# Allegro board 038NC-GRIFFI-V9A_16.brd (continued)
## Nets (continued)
DGND: BD1.1 BD2.1 BR1.2 BR3.2 BR4.2 C14.1 C84.2 C85.2 C86.2 C87.2 C88.2 C89.2 C90.2 C99.2 C100.2 C101.2 C103.2 R378.2 R382.2 SITE1.EPAD1(AVSS[01]) SITE1.F3(AVSS_F[01]) SITE1.F24(PVSS_F) SITE1.G1 SITE1.G2 SITE1.G3 SITE1.G4 SITE1.G5 SITE2.EPAD1(AVSS[01]) SITE2.F3(AVSS_F[01]) SITE2.F24(PVSS_F) SITE2.G1 SITE2.G2 SITE2.G3 SITE2.G4 SITE2.G5 SITE3.EPAD1(AVSS[01]) SITE3.F3(AVSS_F[01]) SITE3.F24(PVSS_F) SITE3.G1 SITE3.G2 SITE3.G3 SITE3.G4 SITE3.G5 SITE4.EPAD1(AVSS[01]) SITE4.F3(AVSS_F[01]) SITE4.F24(PVSS_F) SITE4.G1 SITE4.G2 SITE4.G3 SITE4.G4 SITE4.G5 SITE5.EPAD1(AVSS[01]) SITE5.F3(AVSS_F[01]) SITE5.F24(PVSS_F) SITE5.G1 SITE5.G2 SITE5.G3 SITE5.G4 SITE5.G5 SITE6.EPAD1(AVSS[01]) SITE6.F3(AVSS_F[01]) SITE6.F24(PVSS_F) SITE6.G1 SITE6.G2 SITE6.G3 SITE6.G4 SITE6.G5 SITE7.EPAD1(AVSS[01]) SITE7.F3(AVSS_F[01]) SITE7.F24(PVSS_F) SITE7.G1 SITE7.G2 SITE7.G3 SITE7.G4 SITE7.G5 SITE8.EPAD1(AVSS[01]) SITE8.F3(AVSS_F[01]) SITE8.F24(PVSS_F) SITE8.G1 SITE8.G2 SITE8.G3 SITE8.G4 SITE8.G5 SITE9.EPAD1(AVSS[01]) SITE9.F3(AVSS_F[01]) SITE9.F24(PVSS_F) SITE9.G1 SITE9.G2 SITE9.G3 SITE9.G4 SITE9.G5 SITE10.EPAD1(AVSS[01]) SITE10.F3(AVSS_F[01]) SITE10.F24(PVSS_F) SITE10.G1 SITE10.G2 SITE10.G3 SITE10.G4 SITE10.G5 SITE11.EPAD1(AVSS[01]) SITE11.F3(AVSS_F[01]) SITE11.F24(PVSS_F) SITE11.G1 SITE11.G2 SITE11.G3 SITE11.G4 SITE11.G5 SITE12.EPAD1(AVSS[01]) SITE12.F3(AVSS_F[01]) SITE12.F24(PVSS_F) SITE12.G1 SITE12.G2 SITE12.G3 SITE12.G4 SITE12.G5 SITE13.EPAD1(AVSS[01]) SITE13.F3(AVSS_F[01]) SITE13.F24(PVSS_F) SITE13.G1 SITE13.G2 SITE13.G3 SITE13.G4 SITE13.G5 SITE14.EPAD1(AVSS[01]) SITE14.F3(AVSS_F[01]) SITE14.F24(PVSS_F) SITE14.G1 SITE14.G2 SITE14.G3 SITE14.G4 SITE14.G5 SITE15.EPAD1(AVSS[01]) SITE15.F3(AVSS_F[01]) SITE15.F24(PVSS_F) SITE15.G1 SITE15.G2 SITE15.G3 SITE15.G4 SITE15.G5 SITE16.EPAD1(AVSS[01]) SITE16.F3(AVSS_F[01]) SITE16.F24(PVSS_F) SITE16.G1 SITE16.G2 SITE16.G3 SITE16.G4 SITE16.G5 SLOT0.A9 SLOT0.A10 SLOT0.A11 SLOT0.A12 SLOT0.A13 SLOT0.A14 SLOT0.A15 SLOT0.A17 SLOT0.A38 SLOT0.A42 SLOT0.A44 SLOT0.A46 SLOT0.A50 SLOT0.A52 SLOT0.A53 SLOT0.A54 SLOT0.A56 SLOT0.A57 SLOT0.A58 SLOT0.A60 SLOT0.A61 SLOT0.B9 SLOT0.B11 SLOT0.B13 SLOT0.B15 SLOT0.B17 SLOT0.B38 SLOT0.B42 SLOT0.B44 SLOT0.B46 SLOT0.B48 SLOT0.B50 SLOT0.B51 SLOT0.B52 SLOT0.B54 SLOT0.B55 SLOT0.B56 SLOT0.B58 SLOT0.B59 SLOT0.B60 SLOT0.B62 SLOT0.C9 SLOT0.C11 SLOT0.C12 SLOT0.C13 SLOT0.C15 SLOT0.C17 SLOT0.C42 SLOT0.C44 SLOT0.C46 SLOT0.C48 SLOT0.C50 SLOT0.C52 SLOT0.C53 SLOT0.C54 SLOT0.C56 SLOT0.C57 SLOT0.C58 SLOT0.C60 SLOT0.C61 SLOT0.C62 SLOT0.D9 SLOT0.D10 SLOT0.D11 SLOT0.D13 SLOT0.D14 SLOT0.D15 SLOT0.D42 SLOT0.D44 SLOT0.D46 SLOT0.D48 SLOT0.D50 SLOT0.D51 SLOT0.D52 SLOT0.D54 SLOT0.D55 SLOT0.D56 SLOT0.D58 SLOT0.D59 SLOT0.D60 SLOT0.E9 SLOT0.E11 SLOT0.E12 SLOT0.E13 SLOT0.E15 SLOT0.E42 SLOT0.E44 SLOT0.E46 SLOT0.E48 SLOT0.E50 SLOT0.E52 SLOT0.E53 SLOT0.E54 SLOT0.E56 SLOT0.E57 SLOT0.E58 SLOT0.E60 SLOT0.E61 SLOT0.E62 SLOT0.F9 SLOT0.F11 SLOT0.F13 SLOT0.F15 SLOT0.F42 SLOT0.F44 SLOT0.F46 SLOT0.F48 SLOT0.F50 SLOT0.F51 SLOT0.F52 SLOT0.F54 SLOT0.F55 SLOT0.F56 SLOT0.F58 SLOT0.F59 SLOT0.F60 SLOT0.F62 SLOT0.G10 SLOT0.G12 SLOT0.G42 SLOT0.G44 SLOT0.G46 SLOT0.G50 SLOT0.G52 SLOT0.G54 SLOT0.G56 SLOT0.G58 SLOT0.G60 SLOT3.A6 SLOT3.A8 SLOT3.A10 SLOT3.A12 SLOT3.A14 SLOT3.A16 SLOT3.A18 SLOT3.A20 SLOT3.A22 SLOT3.A24 SLOT3.A26 SLOT3.A28 SLOT3.A30 SLOT3.A32 SLOT3.A34 SLOT3.A36 SLOT3.A38 SLOT3.A40 SLOT3.A42 SLOT3.A44 SLOT3.A46 SLOT3.A48 SLOT3.A50 SLOT3.A52 SLOT3.A54 SLOT3.A56 SLOT3.A58 SLOT3.A60 SLOT3.B6 SLOT3.B8 SLOT3.B10 SLOT3.B12 SLOT3.B14 SLOT3.B16 SLOT3.B18 SLOT3.B20 SLOT3.B22 SLOT3.B24 SLOT3.B26 SLOT3.B28 SLOT3.B30 SLOT3.B32 SLOT3.B34 SLOT3.B36 SLOT3.B38 SLOT3.B40 SLOT3.B42 SLOT3.B44 SLOT3.B46 SLOT3.B48 SLOT3.B50 SLOT3.B52 SLOT3.B54 SLOT3.B56 SLOT3.B58 SLOT3.B60 SLOT3.C6 SLOT3.C8 SLOT3.C10 SLOT3.C12 SLOT3.C14 SLOT3.C16 SLOT3.C18 SLOT3.C20 SLOT3.C22 SLOT3.C24 SLOT3.C26 SLOT3.C28 SLOT3.C30 SLOT3.C32 SLOT3.C34 SLOT3.C36 SLOT3.C38 SLOT3.C40 SLOT3.C42 SLOT3.C44 SLOT3.C46 SLOT3.C48 SLOT3.C50 SLOT3.C52 SLOT3.C54 SLOT3.C56 SLOT3.C58 SLOT3.C60 SLOT3.D6 SLOT3.D8 SLOT3.D10 SLOT3.D12 SLOT3.D14 SLOT3.D16 SLOT3.D18 SLOT3.D20 SLOT3.D22 SLOT3.D24 SLOT3.D26 SLOT3.D28 SLOT3.D30 SLOT3.D32 SLOT3.D34 SLOT3.D36 SLOT3.D38 SLOT3.D40 SLOT3.D42 SLOT3.D44 SLOT3.D46 SLOT3.D48 SLOT3.D50 SLOT3.D52 SLOT3.D54 SLOT3.D56 SLOT3.D58 SLOT3.D60 SLOT3.E6 SLOT3.E8 SLOT3.E10 SLOT3.E12 SLOT3.E14 SLOT3.E16 SLOT3.E18 SLOT3.E20 SLOT3.E22 SLOT3.E24 SLOT3.E26 SLOT3.E28 SLOT3.E30 SLOT3.E32 SLOT3.E34 SLOT3.E36 SLOT3.E38 SLOT3.E40 SLOT3.E42 SLOT3.E44 SLOT3.E46 SLOT3.E48 SLOT3.E50 SLOT3.E52 SLOT3.E54 SLOT3.E56 SLOT3.E58 SLOT3.E60 SLOT3.F6 SLOT3.F8 SLOT3.F10 SLOT3.F12 SLOT3.F14 SLOT3.F16 SLOT3.F18 SLOT3.F20 SLOT3.F22 SLOT3.F24 SLOT3.F26 SLOT3.F28 SLOT3.F30 SLOT3.F32 SLOT3.F34 SLOT3.F36 SLOT3.F38 SLOT3.F40 SLOT3.F42 SLOT3.F44 SLOT3.F46 SLOT3.F48 SLOT3.F50 SLOT3.F52 SLOT3.F54 SLOT3.F56 SLOT3.F58 SLOT3.F60 SLOT4.A6 SLOT4.A8 SLOT4.A10 SLOT4.A12 SLOT4.A14 SLOT4.A16 SLOT4.A18 SLOT4.A20 SLOT4.A22 SLOT4.A24 SLOT4.A26 SLOT4.A28 SLOT4.A30 SLOT4.A32 SLOT4.A34 SLOT4.A36 SLOT4.A38 SLOT4.A40 SLOT4.A42 SLOT4.A44 SLOT4.A46 SLOT4.A48 SLOT4.A50 SLOT4.A52 SLOT4.A54 SLOT4.A56 SLOT4.A58 SLOT4.A60 SLOT4.B6 SLOT4.B8 SLOT4.B10 SLOT4.B12 SLOT4.B14 SLOT4.B16 SLOT4.B18 SLOT4.B20 SLOT4.B22 SLOT4.B24 SLOT4.B26 SLOT4.B28 SLOT4.B30 SLOT4.B32 SLOT4.B34 SLOT4.B36 SLOT4.B38 SLOT4.B40 SLOT4.B42 SLOT4.B44 SLOT4.B46 SLOT4.B48 SLOT4.B50 SLOT4.B52 SLOT4.B54 SLOT4.B56 SLOT4.B58 SLOT4.B60 SLOT4.C6 SLOT4.C8 SLOT4.C10 SLOT4.C12 SLOT4.C14 SLOT4.C16 SLOT4.C18 SLOT4.C20 SLOT4.C22 SLOT4.C24 SLOT4.C26 SLOT4.C28 SLOT4.C30 SLOT4.C32 SLOT4.C34 SLOT4.C36 SLOT4.C38 SLOT4.C40 SLOT4.C42 SLOT4.C44 SLOT4.C46 SLOT4.C48 SLOT4.C50 SLOT4.C52 SLOT4.C54 SLOT4.C56 SLOT4.C58 SLOT4.C60 SLOT4.D6 SLOT4.D8 SLOT4.D10 SLOT4.D12 SLOT4.D14 SLOT4.D16 SLOT4.D18 SLOT4.D20 SLOT4.D22 SLOT4.D24 SLOT4.D26 SLOT4.D28 SLOT4.D30 SLOT4.D32 SLOT4.D34 SLOT4.D36 SLOT4.D38 SLOT4.D40 SLOT4.D42 SLOT4.D44 SLOT4.D46 SLOT4.D48 SLOT4.D50 SLOT4.D52 SLOT4.D54 SLOT4.D56 SLOT4.D58 SLOT4.D60 SLOT4.E6 SLOT4.E8 SLOT4.E10 SLOT4.E12 SLOT4.E14 SLOT4.E16 SLOT4.E18 SLOT4.E20 SLOT4.E22 SLOT4.E24 SLOT4.E26 SLOT4.E28 SLOT4.E30 SLOT4.E32 SLOT4.E34 SLOT4.E36 SLOT4.E38 SLOT4.E40 SLOT4.E42 SLOT4.E44 SLOT4.E46 SLOT4.E48 SLOT4.E50 SLOT4.E52 SLOT4.E54 SLOT4.E56 SLOT4.E58 SLOT4.E60 SLOT4.F6 SLOT4.F8 SLOT4.F10 SLOT4.F12 SLOT4.F14 SLOT4.F16 SLOT4.F18 SLOT4.F20 SLOT4.F22 SLOT4.F24 SLOT4.F26 SLOT4.F28 SLOT4.F30 SLOT4.F32 SLOT4.F34 SLOT4.F36 SLOT4.F38 SLOT4.F40 SLOT4.F42 SLOT4.F44 SLOT4.F46 SLOT4.F48 SLOT4.F50 SLOT4.F52 SLOT4.F54 SLOT4.F56 SLOT4.F58 SLOT4.F60 SLOT6.A2 SLOT6.A6 SLOT6.A10 SLOT6.A14 SLOT6.A18 SLOT6.A22 SLOT6.A26 SLOT6.A30 SLOT6.A34 SLOT6.A38 SLOT6.A42 SLOT6.A46 SLOT6.A50 SLOT6.A54 SLOT6.A58 SLOT6.B4 SLOT6.B8 SLOT6.B12 SLOT6.B16 SLOT6.B20 SLOT6.B24 SLOT6.B28 SLOT6.B32 SLOT6.B36 SLOT6.B40 SLOT6.B44 SLOT6.B48 SLOT6.B52 SLOT6.B56 SLOT6.B60 SLOT6.C2 SLOT6.C6 SLOT6.C10 SLOT6.C14 SLOT6.C18 SLOT6.C22 SLOT6.C26 SLOT6.C30 SLOT6.C34 SLOT6.C38 SLOT6.C42 SLOT6.C46 SLOT6.C50 SLOT6.C54 SLOT6.C58 SLOT6.D4 SLOT6.D8 SLOT6.D12 SLOT6.D16 SLOT6.D20 SLOT6.D24 SLOT6.D28 SLOT6.D32 SLOT6.D36 SLOT6.D40 SLOT6.D44 SLOT6.D48 SLOT6.D52 SLOT6.D56 SLOT6.D60 SLOT6.E2 SLOT6.E6 SLOT6.E10 SLOT6.E14 SLOT6.E18 SLOT6.E22 SLOT6.E26 SLOT6.E30 SLOT6.E34 SLOT6.E38 SLOT6.E42 SLOT6.E46 SLOT6.E50 SLOT6.E54 SLOT6.E58 SLOT6.F4 SLOT6.F8 SLOT6.F12 SLOT6.F16 SLOT6.F20 SLOT6.F24 SLOT6.F28 SLOT6.F32 SLOT6.F36 SLOT6.F40 SLOT6.F44 SLOT6.F48 SLOT6.F52 SLOT6.F56 SLOT6.F60 SLOT6.G2 SLOT6.G6 SLOT6.G10 SLOT6.G14 SLOT6.G18 SLOT6.G22 SLOT6.G26 SLOT6.G30 SLOT6.G34 SLOT6.G38 SLOT6.G42 SLOT6.G46 SLOT6.G50 SLOT6.G54 SLOT6.G58 SLOT7.A2 SLOT7.A6 SLOT7.A10 SLOT7.A14 SLOT7.A18 SLOT7.A22 SLOT7.A26 SLOT7.A30 SLOT7.A34 SLOT7.A38 SLOT7.A42 SLOT7.A46 SLOT7.A50 SLOT7.A54 SLOT7.A58 SLOT7.B4 SLOT7.B8 SLOT7.B12 SLOT7.B16 SLOT7.B20 SLOT7.B24 SLOT7.B28 SLOT7.B32 SLOT7.B36 SLOT7.B40 SLOT7.B44 SLOT7.B48 SLOT7.B52 SLOT7.B56 SLOT7.B60 SLOT7.C2 SLOT7.C6 SLOT7.C10 SLOT7.C14 SLOT7.C18 SLOT7.C22 SLOT7.C26 SLOT7.C30 SLOT7.C34 SLOT7.C38 SLOT7.C42 SLOT7.C46 SLOT7.C50 SLOT7.C54 SLOT7.C58 SLOT7.D4 SLOT7.D8 SLOT7.D12 SLOT7.D16 SLOT7.D20 SLOT7.D24 SLOT7.D28 SLOT7.D32 SLOT7.D36 SLOT7.D40 SLOT7.D44 SLOT7.D48 SLOT7.D52 SLOT7.D56 SLOT7.D60 SLOT7.E2 SLOT7.E6 SLOT7.E10 SLOT7.E14 SLOT7.E18 SLOT7.E22 SLOT7.E26 SLOT7.E30 SLOT7.E34 SLOT7.E38 SLOT7.E42 SLOT7.E46 SLOT7.E50 SLOT7.E54 SLOT7.E58 SLOT7.F4 SLOT7.F8 SLOT7.F12 SLOT7.F16 SLOT7.F20 SLOT7.F24 SLOT7.F28 SLOT7.F32 SLOT7.F36 SLOT7.F40 SLOT7.F44 SLOT7.F48 SLOT7.F52 SLOT7.F56 SLOT7.F60 SLOT7.G2 SLOT7.G6 SLOT7.G10 SLOT7.G14 SLOT7.G18 SLOT7.G22 SLOT7.G26 SLOT7.G30 SLOT7.G34 SLOT7.G38 SLOT7.G42 SLOT7.G46 SLOT7.G50 SLOT7.G54 SLOT7.G58 SLOT8.A2 SLOT8.A6 SLOT8.A10 SLOT8.A14 SLOT8.A18 SLOT8.A22 SLOT8.A26 SLOT8.A30 SLOT8.A34 SLOT8.A38 SLOT8.A42 SLOT8.A46 SLOT8.A50 SLOT8.A54 SLOT8.A58 SLOT8.B4 SLOT8.B8 SLOT8.B12 SLOT8.B16 SLOT8.B20 SLOT8.B24 SLOT8.B28 SLOT8.B32 SLOT8.B36 SLOT8.B40 SLOT8.B44 SLOT8.B48 SLOT8.B52 SLOT8.B56 SLOT8.B60 SLOT8.C2 SLOT8.C6 SLOT8.C10 SLOT8.C14 SLOT8.C18 SLOT8.C22 SLOT8.C26 SLOT8.C30 SLOT8.C34 SLOT8.C38 SLOT8.C42 SLOT8.C46 SLOT8.C50 SLOT8.C54 SLOT8.C58 SLOT8.D4 SLOT8.D8 SLOT8.D12 SLOT8.D16 SLOT8.D20 SLOT8.D24 SLOT8.D28 SLOT8.D32 SLOT8.D36 SLOT8.D40 SLOT8.D44 SLOT8.D48 SLOT8.D52 SLOT8.D56 SLOT8.D60 SLOT8.E2 SLOT8.E6 SLOT8.E10 SLOT8.E14 SLOT8.E18 SLOT8.E22 SLOT8.E26 SLOT8.E30 SLOT8.E34 SLOT8.E38 SLOT8.E42 SLOT8.E46 SLOT8.E50 SLOT8.E54 SLOT8.E58 SLOT8.F4 SLOT8.F8 SLOT8.F12 SLOT8.F16 SLOT8.F20 SLOT8.F24 SLOT8.F28 SLOT8.F32 SLOT8.F36 SLOT8.F40 SLOT8.F44 SLOT8.F48 SLOT8.F52 SLOT8.F56 SLOT8.F60 SLOT8.G2 SLOT8.G6 SLOT8.G10 SLOT8.G14 SLOT8.G18 SLOT8.G22 SLOT8.G26 SLOT8.G30 SLOT8.G34 SLOT8.G38 SLOT8.G42 SLOT8.G46 SLOT8.G50 SLOT8.G54 SLOT8.G58 SLOT9.A2 SLOT9.A6 SLOT9.A10 SLOT9.A14 SLOT9.A18 SLOT9.A22 SLOT9.A26 SLOT9.A30 SLOT9.A34 SLOT9.A38 SLOT9.A42 SLOT9.A46 SLOT9.A50 SLOT9.A54 SLOT9.A58 SLOT9.B4 SLOT9.B8 SLOT9.B12 SLOT9.B16 SLOT9.B20 SLOT9.B24 SLOT9.B28 SLOT9.B32 SLOT9.B36 SLOT9.B40 SLOT9.B44 SLOT9.B48 SLOT9.B52 SLOT9.B56 SLOT9.B60 SLOT9.C2 SLOT9.C6 SLOT9.C10 SLOT9.C14 SLOT9.C18 SLOT9.C22 SLOT9.C26 SLOT9.C30 SLOT9.C34 SLOT9.C38 SLOT9.C42 SLOT9.C46 SLOT9.C50 SLOT9.C54 SLOT9.C58 SLOT9.D4 SLOT9.D8 SLOT9.D12 SLOT9.D16 SLOT9.D20 SLOT9.D24 SLOT9.D28 SLOT9.D32 SLOT9.D36 SLOT9.D40 SLOT9.D44 SLOT9.D48 SLOT9.D52 SLOT9.D56 SLOT9.D60 SLOT9.E2 SLOT9.E6 SLOT9.E10 SLOT9.E14 SLOT9.E18 SLOT9.E22 SLOT9.E26 SLOT9.E30 SLOT9.E34 SLOT9.E38 SLOT9.E42 SLOT9.E46 SLOT9.E50 SLOT9.E54 SLOT9.E58 SLOT9.F4 SLOT9.F8 SLOT9.F12 SLOT9.F16 SLOT9.F20 SLOT9.F24 SLOT9.F28 SLOT9.F32 SLOT9.F36 SLOT9.F40 SLOT9.F44 SLOT9.F48 SLOT9.F52 SLOT9.F56 SLOT9.F60 SLOT9.G2 SLOT9.G6 SLOT9.G10 SLOT9.G14 SLOT9.G18 SLOT9.G22 SLOT9.G26 SLOT9.G30 SLOT9.G34 SLOT9.G38 SLOT9.G42 SLOT9.G46 SLOT9.G50 SLOT9.G54 SLOT9.G58 SLOT10.A2 SLOT10.A6 SLOT10.A10 SLOT10.A14 SLOT10.A18 SLOT10.A22 SLOT10.A26 SLOT10.A30 SLOT10.A34 SLOT10.A38 SLOT10.A42 SLOT10.A46 SLOT10.A50 SLOT10.A54 SLOT10.A58 SLOT10.B4 SLOT10.B8 SLOT10.B12 SLOT10.B16 SLOT10.B20 SLOT10.B24 SLOT10.B28 SLOT10.B32 SLOT10.B36 SLOT10.B40 SLOT10.B44 SLOT10.B48 SLOT10.B52 SLOT10.B56 SLOT10.B60 SLOT10.C2 SLOT10.C6 SLOT10.C10 SLOT10.C14 SLOT10.C18 SLOT10.C22 SLOT10.C26 SLOT10.C30 SLOT10.C34 SLOT10.C38 SLOT10.C42 SLOT10.C46 SLOT10.C50 SLOT10.C54 SLOT10.C58 SLOT10.D4 SLOT10.D8 SLOT10.D12 SLOT10.D16 SLOT10.D20 SLOT10.D24 SLOT10.D28 SLOT10.D32 SLOT10.D36 SLOT10.D40 SLOT10.D44 SLOT10.D48 SLOT10.D52 SLOT10.D56 SLOT10.D60 SLOT10.E2 SLOT10.E6 SLOT10.E10 SLOT10.E14 SLOT10.E18 SLOT10.E22 SLOT10.E26 SLOT10.E30 SLOT10.E34 SLOT10.E38 SLOT10.E42 SLOT10.E46 SLOT10.E50 SLOT10.E54 SLOT10.E58 SLOT10.F4 SLOT10.F8 SLOT10.F12 SLOT10.F16 SLOT10.F20 SLOT10.F24 SLOT10.F28 SLOT10.F32 SLOT10.F36 SLOT10.F40 SLOT10.F44 SLOT10.F48 SLOT10.F52 SLOT10.F56 SLOT10.F60 SLOT10.G2 SLOT10.G6 SLOT10.G10 SLOT10.G14 SLOT10.G18 SLOT10.G22 SLOT10.G26 SLOT10.G30 SLOT10.G34 SLOT10.G38 SLOT10.G42 SLOT10.G46 SLOT10.G50 SLOT10.G54 SLOT10.G58 SLOT13.A2 SLOT13.A6 SLOT13.A10 SLOT13.A14 SLOT13.A18 SLOT13.A22 SLOT13.A26 SLOT13.A30 SLOT13.A34 SLOT13.A38 SLOT13.A42 SLOT13.A46 SLOT13.A50 SLOT13.A54 SLOT13.A58 SLOT13.B4 SLOT13.B8 SLOT13.B12 SLOT13.B16 SLOT13.B20 SLOT13.B24 SLOT13.B28 SLOT13.B32 SLOT13.B36 SLOT13.B40 SLOT13.B44 SLOT13.B48 SLOT13.B52 SLOT13.B56 SLOT13.B60 SLOT13.C2 SLOT13.C6 SLOT13.C10 SLOT13.C14 SLOT13.C18 SLOT13.C22 SLOT13.C26 SLOT13.C30 SLOT13.C34 SLOT13.C38 SLOT13.C42 SLOT13.C46 SLOT13.C50 SLOT13.C54 SLOT13.C58 SLOT13.D4 SLOT13.D8 SLOT13.D12 SLOT13.D16 SLOT13.D20 SLOT13.D24 SLOT13.D28 SLOT13.D32 SLOT13.D36 SLOT13.D40 SLOT13.D44 SLOT13.D48 SLOT13.D52 SLOT13.D56 SLOT13.D60 SLOT13.E2 SLOT13.E6 SLOT13.E10 SLOT13.E14 SLOT13.E18 SLOT13.E22 SLOT13.E26 SLOT13.E30 SLOT13.E34 SLOT13.E38 SLOT13.E42 SLOT13.E46 SLOT13.E50 SLOT13.E54 SLOT13.E58 SLOT13.F4 SLOT13.F8 SLOT13.F12 SLOT13.F16 SLOT13.F20 SLOT13.F24 SLOT13.F28 SLOT13.F32 SLOT13.F36 SLOT13.F40 SLOT13.F44 SLOT13.F48 SLOT13.F52 SLOT13.F56 SLOT13.F60 SLOT13.G2 SLOT13.G6 SLOT13.G10 SLOT13.G14 SLOT13.G18 SLOT13.G22 SLOT13.G26 SLOT13.G30 SLOT13.G34 SLOT13.G38 SLOT13.G42 SLOT13.G46 SLOT13.G50 SLOT13.G54 SLOT13.G58 SLOT17.A6 SLOT17.A8 SLOT17.A10 SLOT17.A12 SLOT17.A14 SLOT17.A16 SLOT17.A18 SLOT17.A20 SLOT17.A22 SLOT17.A24 SLOT17.A26 SLOT17.A28 SLOT17.A30 SLOT17.A32 SLOT17.A34 SLOT17.A36 SLOT17.A38 SLOT17.A40 SLOT17.A42 SLOT17.A44 SLOT17.A46 SLOT17.A48 SLOT17.A50 SLOT17.A52 SLOT17.A54 SLOT17.A56 SLOT17.A58 SLOT17.A60 SLOT17.B6 SLOT17.B8 SLOT17.B10 SLOT17.B12 SLOT17.B14 SLOT17.B16 SLOT17.B18 SLOT17.B20 SLOT17.B22 SLOT17.B24 SLOT17.B26 SLOT17.B28 SLOT17.B30 SLOT17.B32 SLOT17.B34 SLOT17.B36 SLOT17.B38 SLOT17.B40 SLOT17.B42 SLOT17.B44 SLOT17.B46 SLOT17.B48 SLOT17.B50 SLOT17.B52 SLOT17.B54 SLOT17.B56 SLOT17.B58 SLOT17.B60 SLOT17.C6 SLOT17.C8 SLOT17.C10 SLOT17.C12 SLOT17.C14 SLOT17.C16 SLOT17.C18 SLOT17.C20 SLOT17.C22 SLOT17.C24 SLOT17.C26 SLOT17.C28 SLOT17.C30 SLOT17.C32 SLOT17.C34 SLOT17.C36 SLOT17.C38 SLOT17.C40 SLOT17.C42 SLOT17.C44 SLOT17.C46 SLOT17.C48 SLOT17.C50 SLOT17.C52 SLOT17.C54 SLOT17.C56 SLOT17.C58 SLOT17.C60 SLOT17.D6 SLOT17.D8 SLOT17.D10 SLOT17.D12 SLOT17.D14 SLOT17.D16 SLOT17.D18 SLOT17.D20 SLOT17.D22 SLOT17.D24 SLOT17.D26 SLOT17.D28 SLOT17.D30 SLOT17.D32 SLOT17.D34 SLOT17.D36 SLOT17.D38 SLOT17.D40 SLOT17.D42 SLOT17.D44 SLOT17.D46 SLOT17.D48 SLOT17.D50 SLOT17.D52 SLOT17.D54 SLOT17.D56 SLOT17.D58 SLOT17.D60 SLOT17.E6 SLOT17.E8 SLOT17.E10 SLOT17.E12 SLOT17.E14 SLOT17.E16 SLOT17.E18 SLOT17.E20 SLOT17.E22 SLOT17.E24 SLOT17.E26 SLOT17.E28 SLOT17.E30 SLOT17.E32 SLOT17.E34 SLOT17.E36 SLOT17.E38 SLOT17.E40 SLOT17.E42 SLOT17.E44 SLOT17.E46 SLOT17.E48 SLOT17.E50 SLOT17.E52 SLOT17.E54 SLOT17.E56 SLOT17.E58 SLOT17.E60 SLOT17.F6 SLOT17.F8 SLOT17.F10 SLOT17.F12 SLOT17.F14 SLOT17.F16 SLOT17.F18 SLOT17.F20 SLOT17.F22 SLOT17.F24 SLOT17.F26 SLOT17.F28 SLOT17.F30 SLOT17.F32 SLOT17.F34 SLOT17.F36 SLOT17.F38 SLOT17.F40 SLOT17.F42 SLOT17.F44 SLOT17.F46 SLOT17.F48 SLOT17.F50 SLOT17.F52 SLOT17.F54 SLOT17.F56 SLOT17.F58 SLOT17.F60 SLOT19.A6 SLOT19.A8 SLOT19.A10 SLOT19.A12 SLOT19.A14 SLOT19.A16 SLOT19.A18 SLOT19.A20 SLOT19.A22 SLOT19.A24 SLOT19.A26 SLOT19.A28 SLOT19.A30 SLOT19.A32 SLOT19.A34 SLOT19.A36 SLOT19.A38 SLOT19.A40 SLOT19.A42 SLOT19.A44 SLOT19.A46 SLOT19.A48 SLOT19.A50 SLOT19.A52 SLOT19.A54 SLOT19.A56 SLOT19.A58 SLOT19.A60 SLOT19.B6 SLOT19.B8 SLOT19.B10 SLOT19.B12 SLOT19.B14 SLOT19.B16 SLOT19.B18 SLOT19.B20 SLOT19.B22 SLOT19.B24 SLOT19.B26 SLOT19.B28 SLOT19.B30 SLOT19.B32 SLOT19.B34 SLOT19.B36 SLOT19.B38 SLOT19.B40 SLOT19.B42 SLOT19.B44 SLOT19.B46 SLOT19.B48 SLOT19.B50 SLOT19.B52 SLOT19.B54 SLOT19.B56 SLOT19.B58 SLOT19.B60 SLOT19.C6 SLOT19.C8 SLOT19.C10 SLOT19.C12 SLOT19.C14 SLOT19.C16 SLOT19.C18 SLOT19.C20 SLOT19.C22 SLOT19.C24 SLOT19.C26 SLOT19.C28 SLOT19.C30 SLOT19.C32 SLOT19.C34 SLOT19.C36 SLOT19.C38 SLOT19.C40 SLOT19.C42 SLOT19.C44 SLOT19.C46 SLOT19.C48 SLOT19.C50 SLOT19.C52 SLOT19.C54 SLOT19.C56 SLOT19.C58 SLOT19.C60 SLOT19.D6 SLOT19.D8 SLOT19.D10 SLOT19.D12 SLOT19.D14 SLOT19.D16 SLOT19.D18 SLOT19.D20 SLOT19.D22 SLOT19.D24 SLOT19.D26 SLOT19.D28 SLOT19.D30 SLOT19.D32 SLOT19.D34 SLOT19.D36 SLOT19.D38 SLOT19.D40 SLOT19.D42 SLOT19.D44 SLOT19.D46 SLOT19.D48 SLOT19.D50 SLOT19.D52 SLOT19.D54 SLOT19.D56 SLOT19.D58 SLOT19.D60 SLOT19.E6 SLOT19.E8 SLOT19.E10 SLOT19.E12 SLOT19.E14 SLOT19.E16 SLOT19.E18 SLOT19.E20 SLOT19.E22 SLOT19.E24 SLOT19.E26 SLOT19.E28 SLOT19.E30 SLOT19.E32 SLOT19.E34 SLOT19.E36 SLOT19.E38 SLOT19.E40 SLOT19.E42 SLOT19.E44 SLOT19.E46 SLOT19.E48 SLOT19.E50 SLOT19.E52 SLOT19.E54 SLOT19.E56 SLOT19.E58 SLOT19.E60 SLOT19.F6 SLOT19.F8 SLOT19.F10 SLOT19.F12 SLOT19.F14 SLOT19.F16 SLOT19.F18 SLOT19.F20 SLOT19.F22 SLOT19.F24 SLOT19.F26 SLOT19.F28 SLOT19.F30 SLOT19.F32 SLOT19.F34 SLOT19.F36 SLOT19.F38 SLOT19.F40 SLOT19.F42 SLOT19.F44 SLOT19.F46 SLOT19.F48 SLOT19.F50 SLOT19.F52 SLOT19.F54 SLOT19.F56 SLOT19.F58 SLOT19.F60 TP_EEP_GND.1(TP) TP_EPP_SCLK_DGND1.1(TP) TP_EPP_SDA_DGND1.1(TP) TP_EPP_VCC_DGND1.1(TP) TP_REG1_P3V3.1(TP) TP_REG1_P_5V_DGND.1(TP) TP_REG1_P_10V_DGND.1(TP) TP_SDUP5V1.1(TP) TP_SDUP15V1.1(TP) TP_USER_GND1.1(TP) TP_USER_SCLK1_DGND1.1(TP) TP_USER_SDA1_DGND1.1(TP) U4.3(A0) U4.4(A1) U4.11(GND) U4.17(EP) U6.1(A0) U6.2(A1) U6.3(A2) U6.4(GND) U6.7(WP) U44.2(GND) UNK0BS1.2 UNK0BS2.2 UNK1C1.2 UNK1C2.1 UNK1C3.2 UNK1C4.1 UNK1C5.2 UNK1C6.2 UNK1C7.2 UNK1C8.2 UNK1C9.2 UNK1C12.2 UNK1CS1.2 UNK1CS4.1 UNK1CS5.1 UNK1CS19.2 UNK1CS20.2 UNK1CS21.2 UNK1CS22.2 UNK1CS23.2 UNK1CS25.2 UNK1CS26.1 UNK1CS27.1 UNK1CS28.2 UNK1R1.1 UNK1R2.2 UNK1R3.2 UNK1R42.2 UNK1RS3.1 UNK1RS4.1 UNK1U1.4 UNK2C1.2 UNK2C2.1 UNK2C3.2 UNK2C4.1 UNK2C5.2 UNK2C6.2 UNK2C7.2 UNK2C8.2 UNK2C9.2 UNK2C12.2 UNK2CS1.2 UNK2CS4.1 UNK2CS5.1 UNK2CS19.2 UNK2CS20.2 UNK2CS21.2 UNK2CS22.2 UNK2CS23.2 UNK2CS25.2 UNK2CS26.1 UNK2CS27.1 UNK2CS28.2 UNK2R1.1 UNK2R2.2 UNK2R3.2 UNK2R42.2 UNK2RS3.1 UNK2RS4.1 UNK2U1.4 UNK3C1.2 UNK3C2.1 UNK3C3.2 UNK3C4.1 UNK3C5.2 UNK3C6.2 UNK3C7.2 UNK3C8.2 UNK3C9.2 UNK3C12.2 UNK3CS1.2 UNK3CS4.1 UNK3CS5.1 UNK3CS19.2 UNK3CS20.2 UNK3CS21.2 UNK3CS22.2 UNK3CS23.2 UNK3CS25.2 UNK3CS26.1 UNK3CS27.1 UNK3CS28.2 UNK3R1.1 UNK3R2.2 UNK3R3.2 UNK3R42.2 UNK3RS3.1 UNK3RS4.1 UNK3U1.4 UNK4C1.2 UNK4C2.1 UNK4C3.2 UNK4C4.1 UNK4C5.2 UNK4C6.2 UNK4C7.2 UNK4C8.2 UNK4C9.2 UNK4C12.2 UNK4CS1.2 UNK4CS4.1 UNK4CS5.1 UNK4CS19.2 UNK4CS20.2 UNK4CS21.2 UNK4CS22.2 UNK4CS23.2 UNK4CS25.2 UNK4CS26.1 UNK4CS27.1 UNK4CS28.2 UNK4R1.1 UNK4R2.2 UNK4R3.2 UNK4R42.2 UNK4RS3.1 UNK4RS4.1 UNK4U1.4 UNK5C1.2 UNK5C2.1 UNK5C3.2 UNK5C4.1 UNK5C5.2 UNK5C6.2 UNK5C7.2 UNK5C8.2 UNK5C9.2 UNK5C12.2 UNK5CS1.2 UNK5CS4.1 UNK5CS5.1 UNK5CS19.2 UNK5CS20.2 UNK5CS21.2 UNK5CS22.2 UNK5CS23.2 UNK5CS25.2 UNK5CS26.1 UNK5CS27.1 UNK5CS28.2 UNK5R1.1 UNK5R2.2 UNK5R3.2 UNK5R42.2 UNK5RS3.1 UNK5RS4.1 UNK5U1.4 UNK6C1.2 UNK6C2.1 UNK6C3.2 UNK6C4.1 UNK6C5.2 UNK6C6.2 UNK6C7.2 UNK6C8.2 UNK6C9.2 UNK6C12.2 UNK6CS1.2 UNK6CS4.1 UNK6CS5.1 UNK6CS19.2 UNK6CS20.2 UNK6CS21.2 UNK6CS22.2 UNK6CS23.2 UNK6CS25.2 UNK6CS26.1 UNK6CS27.1 UNK6CS28.2 UNK6R1.1 UNK6R2.2 UNK6R3.2 UNK6R42.2 UNK6RS3.1 UNK6RS4.1 UNK6U1.4 UNK7C1.2 UNK7C2.1 UNK7C3.2 UNK7C4.1 UNK7C5.2 UNK7C6.2 UNK7C7.2 UNK7C8.2 UNK7C9.2 UNK7C12.2 UNK7CS1.2 UNK7CS4.1 UNK7CS5.1 UNK7CS19.2 UNK7CS20.2 UNK7CS21.2 UNK7CS22.2 UNK7CS23.2 UNK7CS25.2 UNK7CS26.1 UNK7CS27.1 UNK7CS28.2 UNK7R1.1 UNK7R2.2 UNK7R3.2 UNK7R42.2 UNK7RS3.1 UNK7RS4.1 UNK7U1.4 UNK8C1.2 UNK8C2.1 UNK8C3.2 UNK8C4.1 UNK8C5.2 UNK8C6.2 UNK8C7.2 UNK8C8.2 UNK8C9.2 UNK8C12.2 UNK8CS1.2 UNK8CS4.1 UNK8CS5.1 UNK8CS19.2 UNK8CS20.2 UNK8CS21.2 UNK8CS22.2 UNK8CS23.2 UNK8CS25.2 UNK8CS26.1 UNK8CS27.1 UNK8CS28.2 UNK8R1.1 UNK8R2.2 UNK8R3.2 UNK8R42.2 UNK8RS3.1 UNK8RS4.1 UNK8U1.4 UNK9C1.2 UNK9C2.1 UNK9C3.2 UNK9C4.1 UNK9C5.2 UNK9C6.2 UNK9C7.2 UNK9C8.2 UNK9C9.2 UNK9C12.2 UNK9CS1.2 UNK9CS4.1 UNK9CS5.1 UNK9CS19.2 UNK9CS20.2 UNK9CS21.2 UNK9CS22.2 UNK9CS23.2 UNK9CS25.2 UNK9CS26.1 UNK9CS27.1 UNK9CS28.2 UNK9R1.1 UNK9R2.2 UNK9R3.2 UNK9R42.2 UNK9RS3.1 UNK9RS4.1 UNK9U1.4 UNK10C1.2 UNK10C2.1 UNK10C3.2 UNK10C4.1 UNK10C5.2 UNK10C6.2 UNK10C7.2 UNK10C8.2 UNK10C9.2 UNK10C12.2 UNK10CS1.2 UNK10CS4.1 UNK10CS5.1 UNK10CS19.2 UNK10CS20.2 UNK10CS21.2 UNK10CS22.2 UNK10CS23.2 UNK10CS25.2 UNK10CS26.1 UNK10CS27.1 UNK10CS28.2 UNK10R1.1 UNK10R2.2 UNK10R3.2 UNK10R42.2 UNK10RS3.1 UNK10RS4.1 UNK10U1.4 UNK11C1.2 UNK11C2.1 UNK11C3.2 UNK11C4.1 UNK11C5.2 UNK11C6.2 UNK11C7.2 UNK11C8.2 UNK11C9.2 UNK11C12.2 UNK11CS1.2 UNK11CS4.1 UNK11CS5.1 UNK11CS19.2 UNK11CS20.2 UNK11CS21.2 UNK11CS22.2 UNK11CS23.2 UNK11CS25.2 UNK11CS26.1 UNK11CS27.1 UNK11CS28.2 UNK11R1.1 UNK11R2.2 UNK11R3.2 UNK11R42.2 UNK11RS3.1 UNK11RS4.1 UNK11U1.4 UNK12C1.2 UNK12C2.1 UNK12C3.2 UNK12C4.1 UNK12C5.2 UNK12C6.2 UNK12C7.2 UNK12C8.2 UNK12C9.2 UNK12C12.2 UNK12CS1.2 UNK12CS4.1 UNK12CS5.1 UNK12CS19.2 UNK12CS20.2 UNK12CS21.2 UNK12CS22.2 UNK12CS23.2 UNK12CS25.2 UNK12CS26.1 UNK12CS27.1 UNK12CS28.2 UNK12R1.1 UNK12R2.2 UNK12R3.2 UNK12R42.2 UNK12RS3.1 UNK12RS4.1 UNK12U1.4 UNK13C1.2 UNK13C2.1 UNK13C3.2 UNK13C4.1 UNK13C5.2 UNK13C6.2 UNK13C7.2 UNK13C8.2 UNK13C9.2 UNK13C12.2 UNK13CS1.2 UNK13CS4.1 UNK13CS5.1 UNK13CS19.2 UNK13CS20.2 UNK13CS21.2 UNK13CS22.2 UNK13CS23.2 UNK13CS25.2 UNK13CS26.1 UNK13CS27.1 UNK13CS28.2 UNK13R1.1 UNK13R2.2 UNK13R3.2 UNK13R42.2 UNK13RS3.1 UNK13RS4.1 UNK13U1.4 UNK14C1.2 UNK14C2.1 UNK14C3.2 UNK14C4.1 UNK14C5.2 UNK14C6.2 UNK14C7.2 UNK14C8.2 UNK14C9.2 UNK14C12.2 UNK14CS1.2 UNK14CS4.1 UNK14CS5.1 UNK14CS19.2 UNK14CS20.2 UNK14CS21.2 UNK14CS22.2 UNK14CS23.2 UNK14CS25.2 UNK14CS26.1 UNK14CS27.1 UNK14CS28.2 UNK14R1.1 UNK14R2.2 UNK14R3.2 UNK14R42.2 UNK14RS3.1 UNK14RS4.1 UNK14U1.4 UNK15C1.2 UNK15C2.1 UNK15C3.2 UNK15C4.1 UNK15C5.2 UNK15C6.2 UNK15C7.2 UNK15C8.2 UNK15C9.2 UNK15C12.2 UNK15CS1.2 UNK15CS4.1 UNK15CS5.1 UNK15CS19.2 UNK15CS20.2 UNK15CS21.2 UNK15CS22.2 UNK15CS23.2 UNK15CS25.2 UNK15CS26.1 UNK15CS27.1 UNK15CS28.2 UNK15R1.1 UNK15R2.2 UNK15R3.2 UNK15R42.2 UNK15RS3.1 UNK15RS4.1 UNK15U1.4 UNK16C1.2 UNK16C2.1 UNK16C3.2 UNK16C4.1 UNK16C5.2 UNK16C6.2 UNK16C7.2 UNK16C8.2 UNK16C9.2 UNK16C12.2 UNK16CS1.2 UNK16CS4.1 UNK16CS5.1 UNK16CS19.2 UNK16CS20.2 UNK16CS21.2 UNK16CS22.2 UNK16CS23.2 UNK16CS25.2 UNK16CS26.1 UNK16CS27.1 UNK16CS28.2 UNK16R1.1 UNK16R2.2 UNK16R3.2 UNK16R42.2 UNK16RS3.1 UNK16RS4.1 UNK16U1.4 USER_-5V1.1(A)
P5V1: C102.1 FUSE2.2 SDUP5V1.1(TP) U44.1(VIN) U44.3(EN)
P15V1: C99.1 FUSE1.2 SDUP15V1.1(TP) U46.3(IN)
AWGNH1: SLOT0.B53
AWGNH1_MARKER: SLOT0.A45
AWGNH2: SLOT0.C51
AWGNH2_MARKER: SLOT0.B45
AWGNH3: SLOT0.D53
AWGNH3_MARKER: SLOT0.F45
AWGNH4: SLOT0.E51
AWGNH4_MARKER: SLOT0.E45
AWGNH_1_2_TRIG: SLOT0.C47
AWGNH_3_4_TRIG: SLOT0.D47
CLK100_N: SLOT0.E10
CLK100_P: SLOT0.F10
CLKREF50_N: SLOT0.B10
CLKREF50_P: SLOT0.C10
DIGNH1: SLOT0.B61
DIGNH1_DC_OFFSET: SLOT0.C45
DIGNH1_TRIG: SLOT0.B49
DIGNH2: SLOT0.C59
DIGNH2_DC_OFFSET: SLOT0.A43
DIGNH2_TRIG: SLOT0.C49
DIGNH3: SLOT0.B57
DIGNH3_DC_OFFSET: SLOT0.B43
DIGNH3_TRIG: SLOT0.A47
DIGNH4: SLOT0.C55
DIGNH4_DC_OFFSET: SLOT0.C43
DIGNH4_TRIG: SLOT0.B47
DIGNH5: SLOT0.D61
DIGNH5_DC_OFFSET: SLOT0.D45
DIGNH5_TRIG: SLOT0.E49
DIGNH6: SLOT0.E59
DIGNH6_DC_OFFSET: SLOT0.F43
DIGNH6_TRIG: SLOT0.D49
DIGNH7: SLOT0.D57
DIGNH7_DC_OFFSET: SLOT0.E43
DIGNH7_TRIG: SLOT0.F47
DIGNH8: SLOT0.E55
DIGNH8_DC_OFFSET: SLOT0.D43
DIGNH8_TRIG: SLOT0.E47
GX1X_3_GND_SENSE: SLOT3.F19
GX1X_4_GND_SENSE: SLOT4.F19
GX1X_17_GND_SENSE: SLOT17.F19
GX1X_19_GND_SENSE: SLOT19.F19
GX1X_576_3-0: SLOT3.C61
GX1X_577_3-1: SLOT3.D61 UNK9K4.4
GX1X_578_3-2: SITE9.F13(GPIO4_F) SITE9.S13(GPIO4_S) SLOT3.E61 UNK9TP_GPIO4.1
GX1X_579_3-3: SITE9.F12(GPIO3_F) SITE9.S12(GPIO3_S) SLOT3.F61 UNK9TP_GPIO3.1
GX1X_580_3-4: SITE9.F11(GPIO2_F) SITE9.S11(GPIO2_S) SLOT3.A59 UNK9TP_GPIO2.1
GX1X_581_3-5: SITE9.F10(GPIO1_F) SITE9.S10(GPIO1_S) SLOT3.B59 UNK9TP_GPIO1.1
GX1X_582_3-6: SITE9.F9(GPIO0_F) SITE9.S9(GPIO0_S) SLOT3.C59 UNK9TP_GPIO0.1
GX1X_583_3-7: SLOT3.D59 UNK9K3.4
GX1X_584_3-8: SITE9.F6(EN / SHPHLD_F) SLOT3.E59 UNK9TP_SHPHLD_F.1
GX1X_585_3-9: SITE9.S6(EN / SHPHLD_S) SLOT3.F59 UNK9TP_SHPHLD_S.1
GX1X_586_3-10: SLOT3.Z59 UNK9SH36.1 UNK9TP_LSOUT1_G.1
GX1X_587_3-11: SLOT3.Z57 UNK9SH35.1 UNK9TP_LSIN1_G.1
GX1X_588_3-12: SITE9.F2(AVSS2/TST_F) SITE9.S2(AVSS2/TST_S) SLOT3.A57 UNK9TP_AVSS2/TST.1
GX1X_589_3-13: SLOT3.B57 UNK9K13.2 UNK9TP_NPG/ATB1_G.1
GX1X_590_3-14: SLOT3.C57 UNK9K14.2 UNK9TP_NCHG/ATB0_G.1
GX1X_591_3-15: SLOT3.D57 UNK9SH37.1 UNK9TP_LSIN2/NCHGEN_G.1
GX1X_592_3-16: SLOT3.E57 UNK9SH38.1 UNK9TP_LSOUT2/SUSPEND1_G.1
GX1X_593_3-17: SITE9.F18(LED0_F) SITE9.S18(LED0_S) SLOT3.F57 UNK9TP_LED0.1
GX1X_594_3-18: SITE9.F17(LED1_F) SITE9.S17(LED1_S) SLOT3.A55 UNK9TP_LED1.1
GX1X_595_3-19: SITE9.F16(LED2_F) SITE9.S16(LED2_S) SLOT3.B55 UNK9TP_LED2.1
GX1X_596_3-20: SLOT3.C55 UNK9SH40.1
GX1X_597_3-21: SLOT3.D55 UNK9SH41.1
GX1X_598_3-22: SLOT3.E55
GX1X_599_3-23: SLOT3.F55
GX1X_600_3-24: SLOT3.Z55
GX1X_601_3-25: SLOT3.Z53 UNK11K4.4
GX1X_602_3-26: SITE11.F13(GPIO4_F) SITE11.S13(GPIO4_S) SLOT3.A53 UNK11TP_GPIO4.1
GX1X_603_3-27: SITE11.F12(GPIO3_F) SITE11.S12(GPIO3_S) SLOT3.B53 UNK11TP_GPIO3.1
GX1X_604_3-28: SITE11.F11(GPIO2_F) SITE11.S11(GPIO2_S) SLOT3.C53 UNK11TP_GPIO2.1
GX1X_605_3-29: SITE11.F10(GPIO1_F) SITE11.S10(GPIO1_S) SLOT3.D53 UNK11TP_GPIO1.1
GX1X_606_3-30: SITE11.F9(GPIO0_F) SITE11.S9(GPIO0_S) SLOT3.E53 UNK11TP_GPIO0.1
GX1X_607_3-31: SLOT3.F53 UNK11K3.4
GX1X_608_3-32: SITE11.F6(EN / SHPHLD_F) SLOT3.A51 UNK11TP_SHPHLD_F.1
GX1X_609_3-33: SITE11.S6(EN / SHPHLD_S) SLOT3.B51 UNK11TP_SHPHLD_S.1
GX1X_610_3-34: SLOT3.C51 UNK11SH36.1 UNK11TP_LSOUT1_G.1
GX1X_611_3-35: SLOT3.D51 UNK11SH35.1 UNK11TP_LSIN1_G.1
GX1X_612_3-36: SITE11.F2(AVSS2/TST_F) SITE11.S2(AVSS2/TST_S) SLOT3.E51 UNK11TP_AVSS2/TST.1
GX1X_613_3-37: SLOT3.F51 UNK11K13.2 UNK11TP_NPG/ATB1_G.1
GX1X_614_3-38: SLOT3.A49 UNK11K14.2 UNK11TP_NCHG/ATB0_G.1
GX1X_615_3-39: SLOT3.B49 UNK11SH37.1 UNK11TP_LSIN2/NCHGEN_G.1
GX1X_616_3-40: SLOT3.C49 UNK11SH38.1 UNK11TP_LSOUT2/SUSPEND1_G.1
GX1X_617_3-41: SITE11.F18(LED0_F) SITE11.S18(LED0_S) SLOT3.D49 UNK11TP_LED0.1
GX1X_618_3-42: SITE11.F17(LED1_F) SITE11.S17(LED1_S) SLOT3.E49 UNK11TP_LED1.1
GX1X_619_3-43: SITE11.F16(LED2_F) SITE11.S16(LED2_S) SLOT3.F49 UNK11TP_LED2.1
GX1X_620_3-44: SLOT3.Z49 UNK11SH40.1
GX1X_621_3-45: SLOT3.Z47 UNK11SH41.1
GX1X_622_3-46: SLOT3.A47
GX1X_623_3-47: SLOT3.B47
GX1X_624_3-48: SLOT3.C47
GX1X_625_3-49: SLOT3.D47 UNK13K4.4
GX1X_626_3-50: SITE13.F13(GPIO4_F) SITE13.S13(GPIO4_S) SLOT3.E47 UNK13TP_GPIO4.1
GX1X_627_3-51: SITE13.F12(GPIO3_F) SITE13.S12(GPIO3_S) SLOT3.F47 UNK13TP_GPIO3.1
GX1X_628_3-52: SITE13.F11(GPIO2_F) SITE13.S11(GPIO2_S) SLOT3.A45 UNK13TP_GPIO2.1
GX1X_629_3-53: SITE13.F10(GPIO1_F) SITE13.S10(GPIO1_S) SLOT3.B45 UNK13TP_GPIO1.1
GX1X_630_3-54: SITE13.F9(GPIO0_F) SITE13.S9(GPIO0_S) SLOT3.C45 UNK13TP_GPIO0.1
GX1X_631_3-55: SLOT3.D45 UNK13K3.4
GX1X_632_3-56: SITE13.F6(EN / SHPHLD_F) SLOT3.E45 UNK13TP_SHPHLD_F.1
GX1X_633_3-57: SITE13.S6(EN / SHPHLD_S) SLOT3.F45 UNK13TP_SHPHLD_S.1
GX1X_634_3-58: SLOT3.Z45 UNK13SH36.1 UNK13TP_LSOUT1_G.1
GX1X_635_3-59: SLOT3.Z43 UNK13SH35.1 UNK13TP_LSIN1_G.1
GX1X_636_3-60: SITE13.F2(AVSS2/TST_F) SITE13.S2(AVSS2/TST_S) SLOT3.A43 UNK13TP_AVSS2/TST.1
GX1X_637_3-61: SLOT3.B43 UNK13K13.2 UNK13TP_NPG/ATB1_G.1
GX1X_638_3-62: SLOT3.C43 UNK13K14.2 UNK13TP_NCHG/ATB0_G.1
GX1X_639_3-63: SLOT3.D43 UNK13SH37.1 UNK13TP_LSIN2/NCHGEN_G.1
GX1X_640_3-64: SLOT3.A37 UNK13SH38.1 UNK13TP_LSOUT2/SUSPEND1_G.1
GX1X_641_3-65: SITE13.F18(LED0_F) SITE13.S18(LED0_S) SLOT3.B37 UNK13TP_LED0.1
GX1X_642_3-66: SITE13.F17(LED1_F) SITE13.S17(LED1_S) SLOT3.C37 UNK13TP_LED1.1
GX1X_643_3-67: SITE13.F16(LED2_F) SITE13.S16(LED2_S) SLOT3.D37 UNK13TP_LED2.1
GX1X_644_3-68: SLOT3.E37 UNK13SH40.1
GX1X_645_3-69: SLOT3.F37 UNK13SH41.1
GX1X_646_3-70: SLOT3.A35
GX1X_647_3-71: SLOT3.B35
GX1X_648_3-72: SLOT3.C35
GX1X_649_3-73: SLOT3.D35 UNK15K4.4
GX1X_650_3-74: SITE15.F13(GPIO4_F) SITE15.S13(GPIO4_S) SLOT3.E35 UNK15TP_GPIO4.1
GX1X_651_3-75: SITE15.F12(GPIO3_F) SITE15.S12(GPIO3_S) SLOT3.F35 UNK15TP_GPIO3.1
GX1X_652_3-76: SITE15.F11(GPIO2_F) SITE15.S11(GPIO2_S) SLOT3.Z35 UNK15TP_GPIO2.1
GX1X_653_3-77: SITE15.F10(GPIO1_F) SITE15.S10(GPIO1_S) SLOT3.Z33 UNK15TP_GPIO1.1
GX1X_654_3-78: SITE15.F9(GPIO0_F) SITE15.S9(GPIO0_S) SLOT3.A33 UNK15TP_GPIO0.1
GX1X_655_3-79: SLOT3.B33 UNK15K3.4
GX1X_656_3-80: SITE15.F6(EN / SHPHLD_F) SLOT3.C33 UNK15TP_SHPHLD_F.1
GX1X_657_3-81: SITE15.S6(EN / SHPHLD_S) SLOT3.D33 UNK15TP_SHPHLD_S.1
GX1X_658_3-82: SLOT3.E33 UNK15SH36.1 UNK15TP_LSOUT1_G.1
GX1X_659_3-83: SLOT3.F33 UNK15SH35.1 UNK15TP_LSIN1_G.1
GX1X_660_3-84: SITE15.F2(AVSS2/TST_F) SITE15.S2(AVSS2/TST_S) SLOT3.A31 UNK15TP_AVSS2/TST.1
GX1X_661_3-85: SLOT3.B31 UNK15K13.2 UNK15TP_NPG/ATB1_G.1
GX1X_662_3-86: SLOT3.C31 UNK15K14.2 UNK15TP_NCHG/ATB0_G.1
GX1X_663_3-87: SLOT3.D31 UNK15SH37.1 UNK15TP_LSIN2/NCHGEN_G.1
GX1X_664_3-88: SLOT3.E31 UNK15SH38.1 UNK15TP_LSOUT2/SUSPEND1_G.1
GX1X_665_3-89: SITE15.F18(LED0_F) SITE15.S18(LED0_S) SLOT3.F31 UNK15TP_LED0.1
GX1X_666_3-90: SITE15.F17(LED1_F) SITE15.S17(LED1_S) SLOT3.Z31 UNK15TP_LED1.1
GX1X_667_3-91: SITE15.F16(LED2_F) SITE15.S16(LED2_S) SLOT3.Z29 UNK15TP_LED2.1
GX1X_668_3-92: SLOT3.A29 UNK15SH40.1
GX1X_669_3-93: SLOT3.B29 UNK15SH41.1
GX1X_670_3-94: SLOT3.C29
GX1X_671_3-95: SLOT3.D29
GX1X_672_3-96: SLOT3.E29 UNK7K3.4
GX1X_673_3-97: SITE7.F9(GPIO0_F) SITE7.S9(GPIO0_S) SLOT3.F29 UNK7TP_GPIO0.1
GX1X_674_3-98: SITE7.F10(GPIO1_F) SITE7.S10(GPIO1_S) SLOT3.A27 UNK7TP_GPIO1.1
GX1X_675_3-99: SITE7.F11(GPIO2_F) SITE7.S11(GPIO2_S) SLOT3.B27 UNK7TP_GPIO2.1
GX1X_676_3-100: SITE7.F12(GPIO3_F) SITE7.S12(GPIO3_S) SLOT3.C27 UNK7TP_GPIO3.1
GX1X_677_3-101: SITE7.F13(GPIO4_F) SITE7.S13(GPIO4_S) SLOT3.D27 UNK7TP_GPIO4.1
GX1X_678_3-102: SLOT3.E27 UNK7K4.4
GX1X_679_3-103: SLOT3.F27
GX1X_680_3-104: SLOT3.Z27
GX1X_681_3-105: SLOT3.Z25
GX1X_682_3-106: SLOT3.A25 UNK5SH41.1
GX1X_683_3-107: SLOT3.B25 UNK5SH40.1
GX1X_684_3-108: SITE5.F16(LED2_F) SITE5.S16(LED2_S) SLOT3.C25 UNK5TP_LED2.1
GX1X_685_3-109: SITE5.F17(LED1_F) SITE5.S17(LED1_S) SLOT3.D25 UNK5TP_LED1.1
GX1X_686_3-110: SITE5.F18(LED0_F) SITE5.S18(LED0_S) SLOT3.E25 UNK5TP_LED0.1
GX1X_687_3-111: SLOT3.F25 UNK5SH38.1 UNK5TP_LSOUT2/SUSPEND1_G.1
GX1X_688_3-112: SLOT3.A23 UNK5SH37.1 UNK5TP_LSIN2/NCHGEN_G.1
GX1X_689_3-113: SLOT3.B23 UNK5K14.2 UNK5TP_NCHG/ATB0_G.1
GX1X_690_3-114: SLOT3.C23 UNK5K13.2 UNK5TP_NPG/ATB1_G.1
GX1X_691_3-115: SITE5.F2(AVSS2/TST_F) SITE5.S2(AVSS2/TST_S) SLOT3.D23 UNK5TP_AVSS2/TST.1
GX1X_692_3-116: SLOT3.E23 UNK5SH35.1 UNK5TP_LSIN1_G.1
GX1X_693_3-117: SLOT3.F23 UNK5SH36.1 UNK5TP_LSOUT1_G.1
GX1X_694_3-118: SITE5.F6(EN / SHPHLD_F) SLOT3.Z23 UNK5TP_SHPHLD_F.1
GX1X_695_3-119: SITE5.S6(EN / SHPHLD_S) SLOT3.Z21 UNK5TP_SHPHLD_S.1
GX1X_696_3-120: SLOT3.A21 UNK5K3.4
GX1X_697_3-121: SITE5.F9(GPIO0_F) SITE5.S9(GPIO0_S) SLOT3.B21 UNK5TP_GPIO0.1
GX1X_698_3-122: SITE5.F10(GPIO1_F) SITE5.S10(GPIO1_S) SLOT3.C21 UNK5TP_GPIO1.1
GX1X_699_3-123: SITE5.F11(GPIO2_F) SITE5.S11(GPIO2_S) SLOT3.D21 UNK5TP_GPIO2.1
GX1X_700_3-124: SITE5.F12(GPIO3_F) SITE5.S12(GPIO3_S) SLOT3.E21 UNK5TP_GPIO3.1
GX1X_701_3-125: SITE5.F13(GPIO4_F) SITE5.S13(GPIO4_S) SLOT3.F21 UNK5TP_GPIO4.1
GX1X_702_3-126: SLOT3.B19 UNK5K4.4
GX1X_703_3-127: SLOT3.C19
GX1X_704_3-128: SLOT3.E43
GX1X_705_3-129: SLOT3.F43
GX1X_706_3-130: SLOT3.A41 UNK7SH41.1
GX1X_707_3-131: SLOT3.B41 UNK7SH40.1
GX1X_708_3-132: SITE7.F16(LED2_F) SITE7.S16(LED2_S) SLOT3.C41 UNK7TP_LED2.1
GX1X_709_3-133: SITE7.F17(LED1_F) SITE7.S17(LED1_S) SLOT3.D41 UNK7TP_LED1.1
GX1X_710_3-134: SITE7.F18(LED0_F) SITE7.S18(LED0_S) SLOT3.E41 UNK7TP_LED0.1
GX1X_711_3-135: SLOT3.F41 UNK7SH38.1 UNK7TP_LSOUT2/SUSPEND1_G.1
GX1X_712_3-136: SLOT3.Z41 UNK7SH37.1 UNK7TP_LSIN2/NCHGEN_G.1
GX1X_713_3-137: SLOT3.Z39 UNK7K14.2 UNK7TP_NCHG/ATB0_G.1
GX1X_714_3-138: SLOT3.A39 UNK7K13.2 UNK7TP_NPG/ATB1_G.1
GX1X_715_3-139: SITE7.F2(AVSS2/TST_F) SITE7.S2(AVSS2/TST_S) SLOT3.B39 UNK7TP_AVSS2/TST.1
GX1X_716_3-140: SLOT3.C39 UNK7SH35.1 UNK7TP_LSIN1_G.1
GX1X_717_3-141: SLOT3.D39 UNK7SH36.1 UNK7TP_LSOUT1_G.1
GX1X_718_3-142: SITE7.F6(EN / SHPHLD_F) SLOT3.E39 UNK7TP_SHPHLD_F.1
GX1X_719_3-143: SITE7.S6(EN / SHPHLD_S) SLOT3.F39 UNK7TP_SHPHLD_S.1
GX1X_720_3-144: SLOT3.A17
GX1X_721_3-145: SLOT3.B17
GX1X_722_3-146: SLOT3.C17 UNK3SH41.1
GX1X_723_3-147: SLOT3.D17 UNK3SH40.1
GX1X_724_3-148: SITE3.F16(LED2_F) SITE3.S16(LED2_S) SLOT3.E17 UNK3TP_LED2.1
GX1X_725_3-149: SITE3.F17(LED1_F) SITE3.S17(LED1_S) SLOT3.F17 UNK3TP_LED1.1
GX1X_726_3-150: SITE3.F18(LED0_F) SITE3.S18(LED0_S) SLOT3.A15 UNK3TP_LED0.1
GX1X_727_3-151: SLOT3.B15 UNK3SH38.1 UNK3TP_LSOUT2/SUSPEND1_G.1
GX1X_728_3-152: SLOT3.C15 UNK3SH37.1 UNK3TP_LSIN2/NCHGEN_G.1
GX1X_729_3-153: SLOT3.D15 UNK3K14.2 UNK3TP_NCHG/ATB0_G.1
GX1X_730_3-154: SLOT3.E15 UNK3K13.2 UNK3TP_NPG/ATB1_G.1
GX1X_731_3-155: SITE3.F2(AVSS2/TST_F) SITE3.S2(AVSS2/TST_S) SLOT3.F15 UNK3TP_AVSS2/TST.1
GX1X_732_3-156: SLOT3.Z15 UNK3SH35.1 UNK3TP_LSIN1_G.1
GX1X_733_3-157: SLOT3.Z13 UNK3SH36.1 UNK3TP_LSOUT1_G.1
GX1X_734_3-158: SITE3.F6(EN / SHPHLD_F) SLOT3.A13 UNK3TP_SHPHLD_F.1
GX1X_735_3-159: SITE3.S6(EN / SHPHLD_S) SLOT3.B13 UNK3TP_SHPHLD_S.1
GX1X_736_3-160: SLOT3.C13 UNK3K3.4
GX1X_737_3-161: SITE3.F9(GPIO0_F) SITE3.S9(GPIO0_S) SLOT3.D13 UNK3TP_GPIO0.1
GX1X_738_3-162: SITE3.F10(GPIO1_F) SITE3.S10(GPIO1_S) SLOT3.E13 UNK3TP_GPIO1.1
GX1X_739_3-163: SITE3.F11(GPIO2_F) SITE3.S11(GPIO2_S) SLOT3.F13 UNK3TP_GPIO2.1
GX1X_740_3-164: SITE3.F12(GPIO3_F) SITE3.S12(GPIO3_S) SLOT3.A11 UNK3TP_GPIO3.1
GX1X_741_3-165: SITE3.F13(GPIO4_F) SITE3.S13(GPIO4_S) SLOT3.B11 UNK3TP_GPIO4.1
GX1X_742_3-166: SLOT3.C11 UNK3K4.4
GX1X_743_3-167: SLOT3.D11
GX1X_744_3-168: SLOT3.E11
GX1X_745_3-169: SLOT3.F11
GX1X_746_3-170: SLOT3.Z11 UNK1SH41.1
GX1X_747_3-171: SLOT3.Z9 UNK1SH40.1
GX1X_748_3-172: SITE1.F16(LED2_F) SITE1.S16(LED2_S) SLOT3.A9 UNK1TP_LED2.1
GX1X_749_3-173: SITE1.F17(LED1_F) SITE1.S17(LED1_S) SLOT3.B9 UNK1TP_LED1.1
GX1X_750_3-174: SITE1.F18(LED0_F) SITE1.S18(LED0_S) SLOT3.C9 UNK1TP_LED0.1
GX1X_751_3-175: SLOT3.D9 UNK1SH38.1 UNK1TP_LSOUT2/SUSPEND1_G.1
GX1X_752_3-176: SLOT3.E9 UNK1SH37.1 UNK1TP_LSIN2/NCHGEN_G.1
GX1X_753_3-177: SLOT3.F9 UNK1K14.2 UNK1TP_NCHG/ATB0_G.1
GX1X_754_3-178: SLOT3.A7 UNK1K13.2 UNK1TP_NPG/ATB1_G.1
GX1X_755_3-179: SITE1.F2(AVSS2/TST_F) SITE1.S2(AVSS2/TST_S) SLOT3.B7 UNK1TP_AVSS2/TST.1
GX1X_756_3-180: SLOT3.C7 UNK1SH35.1 UNK1TP_LSIN1_G.1
GX1X_757_3-181: SLOT3.D7 UNK1SH36.1 UNK1TP_LSOUT1_G.1
GX1X_758_3-182: SITE1.F6(EN / SHPHLD_F) SLOT3.E7 UNK1TP_SHPHLD_F.1
GX1X_759_3-183: SITE1.S6(EN / SHPHLD_S) SLOT3.F7 UNK1TP_SHPHLD_S.1
GX1X_760_3-184: SLOT3.Z7 UNK1K3.4
GX1X_761_3-185: SITE1.F9(GPIO0_F) SITE1.S9(GPIO0_S) SLOT3.Z5 UNK1TP_GPIO0.1
GX1X_762_3-186: SITE1.F10(GPIO1_F) SITE1.S10(GPIO1_S) SLOT3.A5 UNK1TP_GPIO1.1
GX1X_763_3-187: SITE1.F11(GPIO2_F) SITE1.S11(GPIO2_S) SLOT3.B5 UNK1TP_GPIO2.1
GX1X_764_3-188: SITE1.F12(GPIO3_F) SITE1.S12(GPIO3_S) SLOT3.C5 UNK1TP_GPIO3.1
GX1X_765_3-189: SITE1.F13(GPIO4_F) SITE1.S13(GPIO4_S) SLOT3.D5 UNK1TP_GPIO4.1
GX1X_766_3-190: SLOT3.E5 UNK1K4.4
GX1X_767_3-191: SLOT3.F5
GX1X_768_4-0: SLOT4.C61
GX1X_769_4-1: SLOT4.D61 UNK10K4.4
GX1X_770_4-2: SITE10.F13(GPIO4_F) SITE10.S13(GPIO4_S) SLOT4.E61 UNK10TP_GPIO4.1
GX1X_771_4-3: SITE10.F12(GPIO3_F) SITE10.S12(GPIO3_S) SLOT4.F61 UNK10TP_GPIO3.1
GX1X_772_4-4: SITE10.F11(GPIO2_F) SITE10.S11(GPIO2_S) SLOT4.A59 UNK10TP_GPIO2.1
GX1X_773_4-5: SITE10.F10(GPIO1_F) SITE10.S10(GPIO1_S) SLOT4.B59 UNK10TP_GPIO1.1
GX1X_774_4-6: SITE10.F9(GPIO0_F) SITE10.S9(GPIO0_S) SLOT4.C59 UNK10TP_GPIO0.1
GX1X_775_4-7: SLOT4.D59 UNK10K3.4
GX1X_776_4-8: SITE10.F6(EN / SHPHLD_F) SLOT4.E59 UNK10TP_SHPHLD_F.1
GX1X_777_4-9: SITE10.S6(EN / SHPHLD_S) SLOT4.F59 UNK10TP_SHPHLD_S.1
GX1X_778_4-10: SLOT4.Z59 UNK10SH36.1 UNK10TP_LSOUT1_G.1
GX1X_779_4-11: SLOT4.Z57 UNK10SH35.1 UNK10TP_LSIN1_G.1
GX1X_780_4-12: SITE10.F2(AVSS2/TST_F) SITE10.S2(AVSS2/TST_S) SLOT4.A57 UNK10TP_AVSS2/TST.1
GX1X_781_4-13: SLOT4.B57 UNK10K13.2 UNK10TP_NPG/ATB1_G.1
GX1X_782_4-14: SLOT4.C57 UNK10K14.2 UNK10TP_NCHG/ATB0_G.1
GX1X_783_4-15: SLOT4.D57 UNK10SH37.1 UNK10TP_LSIN2/NCHGEN_G.1
GX1X_784_4-16: SLOT4.E57 UNK10SH38.1 UNK10TP_LSOUT2/SUSPEND1_G.1
GX1X_785_4-17: SITE10.F18(LED0_F) SITE10.S18(LED0_S) SLOT4.F57 UNK10TP_LED0.1
GX1X_786_4-18: SITE10.F17(LED1_F) SITE10.S17(LED1_S) SLOT4.A55 UNK10TP_LED1.1
GX1X_787_4-19: SITE10.F16(LED2_F) SITE10.S16(LED2_S) SLOT4.B55 UNK10TP_LED2.1
GX1X_788_4-20: SLOT4.C55 UNK10SH40.1
GX1X_789_4-21: SLOT4.D55 UNK10SH41.1
GX1X_790_4-22: SLOT4.E55
GX1X_791_4-23: SLOT4.F55
GX1X_792_4-24: SLOT4.Z55
GX1X_793_4-25: SLOT4.Z53 UNK12K4.4
GX1X_794_4-26: SITE12.F13(GPIO4_F) SITE12.S13(GPIO4_S) SLOT4.A53 UNK12TP_GPIO4.1
GX1X_795_4-27: SITE12.F12(GPIO3_F) SITE12.S12(GPIO3_S) SLOT4.B53 UNK12TP_GPIO3.1
GX1X_796_4-28: SITE12.F11(GPIO2_F) SITE12.S11(GPIO2_S) SLOT4.C53 UNK12TP_GPIO2.1
GX1X_797_4-29: SITE12.F10(GPIO1_F) SITE12.S10(GPIO1_S) SLOT4.D53 UNK12TP_GPIO1.1
GX1X_798_4-30: SITE12.F9(GPIO0_F) SITE12.S9(GPIO0_S) SLOT4.E53 UNK12TP_GPIO0.1
GX1X_799_4-31: SLOT4.F53 UNK12K3.4
GX1X_800_4-32: SITE12.F6(EN / SHPHLD_F) SLOT4.A51 UNK12TP_SHPHLD_F.1
GX1X_801_4-33: SITE12.S6(EN / SHPHLD_S) SLOT4.B51 UNK12TP_SHPHLD_S.1
GX1X_802_4-34: SLOT4.C51 UNK12SH36.1 UNK12TP_LSOUT1_G.1
GX1X_803_4-35: SLOT4.D51 UNK12SH35.1 UNK12TP_LSIN1_G.1
GX1X_804_4-36: SITE12.F2(AVSS2/TST_F) SITE12.S2(AVSS2/TST_S) SLOT4.E51 UNK12TP_AVSS2/TST.1
GX1X_805_4-37: SLOT4.F51 UNK12K13.2 UNK12TP_NPG/ATB1_G.1
GX1X_806_4-38: SLOT4.A49 UNK12K14.2 UNK12TP_NCHG/ATB0_G.1
GX1X_807_4-39: SLOT4.B49 UNK12SH37.1 UNK12TP_LSIN2/NCHGEN_G.1
GX1X_808_4-40: SLOT4.C49 UNK12SH38.1 UNK12TP_LSOUT2/SUSPEND1_G.1
GX1X_809_4-41: SITE12.F18(LED0_F) SITE12.S18(LED0_S) SLOT4.D49 UNK12TP_LED0.1
GX1X_810_4-42: SITE12.F17(LED1_F) SITE12.S17(LED1_S) SLOT4.E49 UNK12TP_LED1.1
GX1X_811_4-43: SITE12.F16(LED2_F) SITE12.S16(LED2_S) SLOT4.F49 UNK12TP_LED2.1
GX1X_812_4-44: SLOT4.Z49 UNK12SH40.1
GX1X_813_4-45: SLOT4.Z47 UNK12SH41.1
GX1X_814_4-46: SLOT4.A47
GX1X_815_4-47: SLOT4.B47
GX1X_816_4-48: SLOT4.C47
GX1X_817_4-49: SLOT4.D47 UNK14K4.4
GX1X_818_4-50: SITE14.F13(GPIO4_F) SITE14.S13(GPIO4_S) SLOT4.E47 UNK14TP_GPIO4.1
GX1X_819_4-51: SITE14.F12(GPIO3_F) SITE14.S12(GPIO3_S) SLOT4.F47 UNK14TP_GPIO3.1
GX1X_820_4-52: SITE14.F11(GPIO2_F) SITE14.S11(GPIO2_S) SLOT4.A45 UNK14TP_GPIO2.1
GX1X_821_4-53: SITE14.F10(GPIO1_F) SITE14.S10(GPIO1_S) SLOT4.B45 UNK14TP_GPIO1.1
GX1X_822_4-54: SITE14.F9(GPIO0_F) SITE14.S9(GPIO0_S) SLOT4.C45 UNK14TP_GPIO0.1
GX1X_823_4-55: SLOT4.D45 UNK14K3.4
GX1X_824_4-56: SITE14.F6(EN / SHPHLD_F) SLOT4.E45 UNK14TP_SHPHLD_F.1
GX1X_825_4-57: SITE14.S6(EN / SHPHLD_S) SLOT4.F45 UNK14TP_SHPHLD_S.1
GX1X_826_4-58: SLOT4.Z45 UNK14SH36.1 UNK14TP_LSOUT1_G.1
GX1X_827_4-59: SLOT4.Z43 UNK14SH35.1 UNK14TP_LSIN1_G.1
GX1X_828_4-60: SITE14.F2(AVSS2/TST_F) SITE14.S2(AVSS2/TST_S) SLOT4.A43 UNK14TP_AVSS2/TST.1
GX1X_829_4-61: SLOT4.B43 UNK14K13.2 UNK14TP_NPG/ATB1_G.1
GX1X_830_4-62: SLOT4.C43 UNK14K14.2 UNK14TP_NCHG/ATB0_G.1
GX1X_831_4-63: SLOT4.D43 UNK14SH37.1 UNK14TP_LSIN2/NCHGEN_G.1
GX1X_832_4-64: SLOT4.A37 UNK14SH38.1 UNK14TP_LSOUT2/SUSPEND1_G.1
GX1X_833_4-65: SITE14.F18(LED0_F) SITE14.S18(LED0_S) SLOT4.B37 UNK14TP_LED0.1
GX1X_834_4-66: SITE14.F17(LED1_F) SITE14.S17(LED1_S) SLOT4.C37 UNK14TP_LED1.1
GX1X_835_4-67: SITE14.F16(LED2_F) SITE14.S16(LED2_S) SLOT4.D37 UNK14TP_LED2.1
GX1X_836_4-68: SLOT4.E37 UNK14SH40.1
GX1X_837_4-69: SLOT4.F37 UNK14SH41.1
GX1X_838_4-70: SLOT4.A35
GX1X_839_4-71: SLOT4.B35
GX1X_840_4-72: SLOT4.C35
GX1X_841_4-73: SLOT4.D35 UNK16K4.4
GX1X_842_4-74: SITE16.F13(GPIO4_F) SITE16.S13(GPIO4_S) SLOT4.E35 UNK16TP_GPIO4.1
GX1X_843_4-75: SITE16.F12(GPIO3_F) SITE16.S12(GPIO3_S) SLOT4.F35 UNK16TP_GPIO3.1
GX1X_844_4-76: SITE16.F11(GPIO2_F) SITE16.S11(GPIO2_S) SLOT4.Z35 UNK16TP_GPIO2.1
GX1X_845_4-77: SITE16.F10(GPIO1_F) SITE16.S10(GPIO1_S) SLOT4.Z33 UNK16TP_GPIO1.1
GX1X_846_4-78: SITE16.F9(GPIO0_F) SITE16.S9(GPIO0_S) SLOT4.A33 UNK16TP_GPIO0.1
GX1X_847_4-79: SLOT4.B33 UNK16K3.4
GX1X_848_4-80: SITE16.F6(EN / SHPHLD_F) SLOT4.C33 UNK16TP_SHPHLD_F.1
GX1X_849_4-81: SITE16.S6(EN / SHPHLD_S) SLOT4.D33 UNK16TP_SHPHLD_S.1
GX1X_850_4-82: SLOT4.E33 UNK16SH36.1 UNK16TP_LSOUT1_G.1
GX1X_851_4-83: SLOT4.F33 UNK16SH35.1 UNK16TP_LSIN1_G.1
GX1X_852_4-84: SITE16.F2(AVSS2/TST_F) SITE16.S2(AVSS2/TST_S) SLOT4.A31 UNK16TP_AVSS2/TST.1
GX1X_853_4-85: SLOT4.B31 UNK16K13.2 UNK16TP_NPG/ATB1_G.1
GX1X_854_4-86: SLOT4.C31 UNK16K14.2 UNK16TP_NCHG/ATB0_G.1
GX1X_855_4-87: SLOT4.D31 UNK16SH37.1 UNK16TP_LSIN2/NCHGEN_G.1
GX1X_856_4-88: SLOT4.E31 UNK16SH38.1 UNK16TP_LSOUT2/SUSPEND1_G.1
GX1X_857_4-89: SITE16.F18(LED0_F) SITE16.S18(LED0_S) SLOT4.F31 UNK16TP_LED0.1
GX1X_858_4-90: SITE16.F17(LED1_F) SITE16.S17(LED1_S) SLOT4.Z31 UNK16TP_LED1.1
GX1X_859_4-91: SITE16.F16(LED2_F) SITE16.S16(LED2_S) SLOT4.Z29 UNK16TP_LED2.1
GX1X_860_4-92: SLOT4.A29 UNK16SH40.1
GX1X_861_4-93: SLOT4.B29 UNK16SH41.1
GX1X_862_4-94: SLOT4.C29
GX1X_863_4-95: SLOT4.D29
GX1X_864_4-96: SLOT4.E29 UNK8K3.4
GX1X_865_4-97: SITE8.F9(GPIO0_F) SITE8.S9(GPIO0_S) SLOT4.F29 UNK8TP_GPIO0.1
GX1X_866_4-98: SITE8.F10(GPIO1_F) SITE8.S10(GPIO1_S) SLOT4.A27 UNK8TP_GPIO1.1
GX1X_867_4-99: SITE8.F11(GPIO2_F) SITE8.S11(GPIO2_S) SLOT4.B27 UNK8TP_GPIO2.1
GX1X_868_4-100: SITE8.F12(GPIO3_F) SITE8.S12(GPIO3_S) SLOT4.C27 UNK8TP_GPIO3.1
GX1X_869_4-101: SITE8.F13(GPIO4_F) SITE8.S13(GPIO4_S) SLOT4.D27 UNK8TP_GPIO4.1
GX1X_870_4-102: SLOT4.E27 UNK8K4.4
GX1X_871_4-103: SLOT4.F27
GX1X_872_4-104: SLOT4.Z27
GX1X_873_4-105: SLOT4.Z25
GX1X_874_4-106: SLOT4.A25 UNK6SH41.1
GX1X_875_4-107: SLOT4.B25 UNK6SH40.1
GX1X_876_4-108: SITE6.F16(LED2_F) SITE6.S16(LED2_S) SLOT4.C25 UNK6TP_LED2.1
GX1X_877_4-109: SITE6.F17(LED1_F) SITE6.S17(LED1_S) SLOT4.D25 UNK6TP_LED1.1
GX1X_878_4-110: SITE6.F18(LED0_F) SITE6.S18(LED0_S) SLOT4.E25 UNK6TP_LED0.1
GX1X_879_4-111: SLOT4.F25 UNK6SH38.1 UNK6TP_LSOUT2/SUSPEND1_G.1
GX1X_880_4-112: SLOT4.A23 UNK6SH37.1 UNK6TP_LSIN2/NCHGEN_G.1
GX1X_881_4-113: SLOT4.B23 UNK6K14.2 UNK6TP_NCHG/ATB0_G.1
GX1X_882_4-114: SLOT4.C23 UNK6K13.2 UNK6TP_NPG/ATB1_G.1
GX1X_883_4-115: SITE6.F2(AVSS2/TST_F) SITE6.S2(AVSS2/TST_S) SLOT4.D23 UNK6TP_AVSS2/TST.1
GX1X_884_4-116: SLOT4.E23 UNK6SH35.1 UNK6TP_LSIN1_G.1
GX1X_885_4-117: SLOT4.F23 UNK6SH36.1 UNK6TP_LSOUT1_G.1
GX1X_886_4-118: SITE6.F6(EN / SHPHLD_F) SLOT4.Z23 UNK6TP_SHPHLD_F.1
GX1X_887_4-119: SITE6.S6(EN / SHPHLD_S) SLOT4.Z21 UNK6TP_SHPHLD_S.1
GX1X_888_4-120: SLOT4.A21 UNK6K3.4
GX1X_889_4-121: SITE6.F9(GPIO0_F) SITE6.S9(GPIO0_S) SLOT4.B21 UNK6TP_GPIO0.1
GX1X_890_4-122: SITE6.F10(GPIO1_F) SITE6.S10(GPIO1_S) SLOT4.C21 UNK6TP_GPIO1.1
GX1X_891_4-123: SITE6.F11(GPIO2_F) SITE6.S11(GPIO2_S) SLOT4.D21 UNK6TP_GPIO2.1
GX1X_892_4-124: SITE6.F12(GPIO3_F) SITE6.S12(GPIO3_S) SLOT4.E21 UNK6TP_GPIO3.1
GX1X_893_4-125: SITE6.F13(GPIO4_F) SITE6.S13(GPIO4_S) SLOT4.F21 UNK6TP_GPIO4.1
GX1X_894_4-126: SLOT4.B19 UNK6K4.4
GX1X_895_4-127: SLOT4.C19
GX1X_896_4-128: SLOT4.E43
GX1X_897_4-129: SLOT4.F43
GX1X_898_4-130: SLOT4.A41 UNK8SH41.1
GX1X_899_4-131: SLOT4.B41 UNK8SH40.1
GX1X_900_4-132: SITE8.F16(LED2_F) SITE8.S16(LED2_S) SLOT4.C41 UNK8TP_LED2.1
GX1X_901_4-133: SITE8.F17(LED1_F) SITE8.S17(LED1_S) SLOT4.D41 UNK8TP_LED1.1
GX1X_902_4-134: SITE8.F18(LED0_F) SITE8.S18(LED0_S) SLOT4.E41 UNK8TP_LED0.1
GX1X_903_4-135: SLOT4.F41 UNK8SH38.1 UNK8TP_LSOUT2/SUSPEND1_G.1
GX1X_904_4-136: SLOT4.Z41 UNK8SH37.1 UNK8TP_LSIN2/NCHGEN_G.1
GX1X_905_4-137: SLOT4.Z39 UNK8K14.2 UNK8TP_NCHG/ATB0_G.1
GX1X_906_4-138: SLOT4.A39 UNK8K13.2 UNK8TP_NPG/ATB1_G.1
GX1X_907_4-139: SITE8.F2(AVSS2/TST_F) SITE8.S2(AVSS2/TST_S) SLOT4.B39 UNK8TP_AVSS2/TST.1
GX1X_908_4-140: SLOT4.C39 UNK8SH35.1 UNK8TP_LSIN1_G.1
GX1X_909_4-141: SLOT4.D39 UNK8SH36.1 UNK8TP_LSOUT1_G.1
GX1X_910_4-142: SITE8.F6(EN / SHPHLD_F) SLOT4.E39 UNK8TP_SHPHLD_F.1
GX1X_911_4-143: SITE8.S6(EN / SHPHLD_S) SLOT4.F39 UNK8TP_SHPHLD_S.1
GX1X_912_4-144: SLOT4.A17
GX1X_913_4-145: SLOT4.B17
GX1X_914_4-146: SLOT4.C17 UNK4SH41.1
GX1X_915_4-147: SLOT4.D17 UNK4SH40.1
GX1X_916_4-148: SITE4.F16(LED2_F) SITE4.S16(LED2_S) SLOT4.E17 UNK4TP_LED2.1
GX1X_917_4-149: SITE4.F17(LED1_F) SITE4.S17(LED1_S) SLOT4.F17 UNK4TP_LED1.1
GX1X_918_4-150: SITE4.F18(LED0_F) SITE4.S18(LED0_S) SLOT4.A15 UNK4TP_LED0.1
GX1X_919_4-151: SLOT4.B15 UNK4SH38.1 UNK4TP_LSOUT2/SUSPEND1_G.1
GX1X_920_4-152: SLOT4.C15 UNK4SH37.1 UNK4TP_LSIN2/NCHGEN_G.1
GX1X_921_4-153: SLOT4.D15 UNK4K14.2 UNK4TP_NCHG/ATB0_G.1
GX1X_922_4-154: SLOT4.E15 UNK4K13.2 UNK4TP_NPG/ATB1_G.1
GX1X_923_4-155: SITE4.F2(AVSS2/TST_F) SITE4.S2(AVSS2/TST_S) SLOT4.F15 UNK4TP_AVSS2/TST.1
GX1X_924_4-156: SLOT4.Z15 UNK4SH35.1 UNK4TP_LSIN1_G.1
GX1X_925_4-157: SLOT4.Z13 UNK4SH36.1 UNK4TP_LSOUT1_G.1
GX1X_926_4-158: SITE4.F6(EN / SHPHLD_F) SLOT4.A13 UNK4TP_SHPHLD_F.1
GX1X_927_4-159: SITE4.S6(EN / SHPHLD_S) SLOT4.B13 UNK4TP_SHPHLD_S.1
GX1X_928_4-160: SLOT4.C13 UNK4K3.4
GX1X_929_4-161: SITE4.F9(GPIO0_F) SITE4.S9(GPIO0_S) SLOT4.D13 UNK4TP_GPIO0.1
GX1X_930_4-162: SITE4.F10(GPIO1_F) SITE4.S10(GPIO1_S) SLOT4.E13 UNK4TP_GPIO1.1
GX1X_931_4-163: SITE4.F11(GPIO2_F) SITE4.S11(GPIO2_S) SLOT4.F13 UNK4TP_GPIO2.1
GX1X_932_4-164: SITE4.F12(GPIO3_F) SITE4.S12(GPIO3_S) SLOT4.A11 UNK4TP_GPIO3.1
GX1X_933_4-165: SITE4.F13(GPIO4_F) SITE4.S13(GPIO4_S) SLOT4.B11 UNK4TP_GPIO4.1
GX1X_934_4-166: SLOT4.C11 UNK4K4.4
GX1X_935_4-167: SLOT4.D11
GX1X_936_4-168: SLOT4.E11
GX1X_937_4-169: SLOT4.F11
GX1X_938_4-170: SLOT4.Z11 UNK2SH41.1
GX1X_939_4-171: SLOT4.Z9 UNK2SH40.1
GX1X_940_4-172: SITE2.F16(LED2_F) SITE2.S16(LED2_S) SLOT4.A9 UNK2TP_LED2.1
GX1X_941_4-173: SITE2.F17(LED1_F) SITE2.S17(LED1_S) SLOT4.B9 UNK2TP_LED1.1
GX1X_942_4-174: SITE2.F18(LED0_F) SITE2.S18(LED0_S) SLOT4.C9 UNK2TP_LED0.1
GX1X_943_4-175: SLOT4.D9 UNK2SH38.1 UNK2TP_LSOUT2/SUSPEND1_G.1
GX1X_944_4-176: SLOT4.E9 UNK2SH37.1 UNK2TP_LSIN2/NCHGEN_G.1
GX1X_945_4-177: SLOT4.F9 UNK2K14.2 UNK2TP_NCHG/ATB0_G.1
GX1X_946_4-178: SLOT4.A7 UNK2K13.2 UNK2TP_NPG/ATB1_G.1
GX1X_947_4-179: SITE2.F2(AVSS2/TST_F) SITE2.S2(AVSS2/TST_S) SLOT4.B7 UNK2TP_AVSS2/TST.1
GX1X_948_4-180: SLOT4.C7 UNK2SH35.1 UNK2TP_LSIN1_G.1
GX1X_949_4-181: SLOT4.D7 UNK2SH36.1 UNK2TP_LSOUT1_G.1
GX1X_950_4-182: SITE2.F6(EN / SHPHLD_F) SLOT4.E7 UNK2TP_SHPHLD_F.1
GX1X_951_4-183: SITE2.S6(EN / SHPHLD_S) SLOT4.F7 UNK2TP_SHPHLD_S.1
GX1X_952_4-184: SLOT4.Z7 UNK2K3.4
GX1X_953_4-185: SITE2.F9(GPIO0_F) SITE2.S9(GPIO0_S) SLOT4.Z5 UNK2TP_GPIO0.1
GX1X_954_4-186: SITE2.F10(GPIO1_F) SITE2.S10(GPIO1_S) SLOT4.A5 UNK2TP_GPIO1.1
GX1X_955_4-187: SITE2.F11(GPIO2_F) SITE2.S11(GPIO2_S) SLOT4.B5 UNK2TP_GPIO2.1
GX1X_956_4-188: SITE2.F12(GPIO3_F) SITE2.S12(GPIO3_S) SLOT4.C5 UNK2TP_GPIO3.1
GX1X_957_4-189: SITE2.F13(GPIO4_F) SITE2.S13(GPIO4_S) SLOT4.D5 UNK2TP_GPIO4.1
GX1X_958_4-190: SLOT4.E5 UNK2K4.4
GX1X_959_4-191: SLOT4.F5
GX1X_3264_17-0: SLOT17.C61
GX1X_3265_17-1: SLOT17.D61
GX1X_3266_17-2: SLOT17.E61
GX1X_3267_17-3: SLOT17.F61
GX1X_3268_17-4: SLOT17.A59
GX1X_3269_17-5: SLOT17.B59
GX1X_3270_17-6: SLOT17.C59
GX1X_3271_17-7: SLOT17.D59
GX1X_3272_17-8: SLOT17.E59
GX1X_3273_17-9: SLOT17.F59
GX1X_3274_17-10: SLOT17.Z59
GX1X_3275_17-11: SLOT17.Z57
GX1X_3276_17-12: SLOT17.A57
GX1X_3277_17-13: SLOT17.B57
GX1X_3278_17-14: SLOT17.C57
GX1X_3279_17-15: SLOT17.D57
GX1X_3280_17-16: SLOT17.E57
GX1X_3281_17-17: SLOT17.F57
GX1X_3282_17-18: SLOT17.A55
GX1X_3283_17-19: SLOT17.B55
GX1X_3284_17-20: SLOT17.C55
GX1X_3285_17-21: SLOT17.D55
GX1X_3286_17-22: SLOT17.E55
GX1X_3287_17-23: SLOT17.F55
GX1X_3288_17-24: SLOT17.Z55
GX1X_3289_17-25: SLOT17.Z53
GX1X_3290_17-26: SLOT17.A53
GX1X_3291_17-27: SLOT17.B53
GX1X_3292_17-28: SLOT17.C53
GX1X_3293_17-29: SLOT17.D53
GX1X_3294_17-30: SLOT17.E53
GX1X_3295_17-31: SLOT17.F53
GX1X_3296_17-32: SLOT17.A51
GX1X_3297_17-33: SLOT17.B51
GX1X_3298_17-34: SLOT17.C51
GX1X_3299_17-35: SLOT17.D51
GX1X_3300_17-36: SLOT17.E51
GX1X_3301_17-37: SLOT17.F51
GX1X_3302_17-38: SLOT17.A49
GX1X_3303_17-39: SLOT17.B49
GX1X_3304_17-40: SLOT17.C49
GX1X_3305_17-41: SLOT17.D49
GX1X_3306_17-42: SLOT17.E49
GX1X_3307_17-43: SLOT17.F49
GX1X_3308_17-44: SLOT17.Z49
GX1X_3309_17-45: SLOT17.Z47
GX1X_3310_17-46: SLOT17.A47
GX1X_3311_17-47: SLOT17.B47
GX1X_3312_17-48: SLOT17.C47
GX1X_3313_17-49: SLOT17.D47
GX1X_3314_17-50: SLOT17.E47
GX1X_3315_17-51: SLOT17.F47
GX1X_3316_17-52: SLOT17.A45
GX1X_3317_17-53: SLOT17.B45
GX1X_3318_17-54: SLOT17.C45
GX1X_3319_17-55: SLOT17.D45
GX1X_3320_17-56: SLOT17.E45
GX1X_3321_17-57: SLOT17.F45
GX1X_3322_17-58: SLOT17.Z45
GX1X_3323_17-59: SLOT17.Z43
GX1X_3324_17-60: SLOT17.A43
GX1X_3325_17-61: SLOT17.B43
GX1X_3326_17-62: SLOT17.C43
GX1X_3327_17-63: SLOT17.D43
GX1X_3328_17-64: SLOT17.A37
GX1X_3329_17-65: SLOT17.B37
GX1X_3330_17-66: SLOT17.C37
GX1X_3331_17-67: SLOT17.D37
GX1X_3332_17-68: SLOT17.E37
GX1X_3333_17-69: SLOT17.F37
GX1X_3334_17-70: SLOT17.A35
GX1X_3335_17-71: SLOT17.B35
GX1X_3336_17-72: SLOT17.C35
GX1X_3337_17-73: SLOT17.D35
GX1X_3338_17-74: SLOT17.E35
GX1X_3339_17-75: SLOT17.F35
GX1X_3340_17-76: SLOT17.Z35
GX1X_3341_17-77: SLOT17.Z33
GX1X_3342_17-78: SLOT17.A33
GX1X_3343_17-79: SLOT17.B33
GX1X_3344_17-80: SLOT17.C33
GX1X_3345_17-81: SLOT17.D33
GX1X_3346_17-82: SLOT17.E33
GX1X_3347_17-83: SLOT17.F33
GX1X_3348_17-84: SLOT17.A31
GX1X_3349_17-85: SLOT17.B31
GX1X_3350_17-86: SLOT17.C31
GX1X_3351_17-87: SLOT17.D31
GX1X_3352_17-88: SLOT17.E31
GX1X_3353_17-89: SLOT17.F31
GX1X_3354_17-90: SLOT17.Z31
GX1X_3355_17-91: SLOT17.Z29
GX1X_3356_17-92: SLOT17.A29
GX1X_3357_17-93: SLOT17.B29
GX1X_3358_17-94: SLOT17.C29
GX1X_3359_17-95: SLOT17.D29
GX1X_3360_17-96: SLOT17.E29
GX1X_3361_17-97: SLOT17.F29
GX1X_3362_17-98: SLOT17.A27
GX1X_3363_17-99: SLOT17.B27
GX1X_3364_17-100: SLOT17.C27
GX1X_3365_17-101: SLOT17.D27
GX1X_3366_17-102: SLOT17.E27
GX1X_3367_17-103: SLOT17.F27
GX1X_3368_17-104: SLOT17.Z27
GX1X_3369_17-105: SLOT17.Z25
GX1X_3370_17-106: SLOT17.A25
GX1X_3371_17-107: SLOT17.B25
GX1X_3372_17-108: SLOT17.C25
GX1X_3373_17-109: SLOT17.D25
GX1X_3374_17-110: SLOT17.E25
GX1X_3375_17-111: SLOT17.F25
GX1X_3376_17-112: SLOT17.A23
GX1X_3377_17-113: SLOT17.B23
GX1X_3378_17-114: SLOT17.C23
GX1X_3379_17-115: SLOT17.D23
GX1X_3380_17-116: SLOT17.E23
GX1X_3381_17-117: SLOT17.F23
GX1X_3382_17-118: SLOT17.Z23
GX1X_3383_17-119: SLOT17.Z21
GX1X_3384_17-120: SLOT17.A21
GX1X_3385_17-121: SLOT17.B21
GX1X_3386_17-122: SLOT17.C21
GX1X_3387_17-123: SLOT17.D21
GX1X_3388_17-124: SLOT17.E21
GX1X_3389_17-125: SLOT17.F21
GX1X_3390_17-126: SLOT17.B19
GX1X_3391_17-127: SLOT17.C19
GX1X_3392_17-128: SLOT17.E43
GX1X_3393_17-129: SLOT17.F43
GX1X_3394_17-130: SLOT17.A41
GX1X_3395_17-131: SLOT17.B41
GX1X_3396_17-132: SLOT17.C41
GX1X_3397_17-133: SLOT17.D41
GX1X_3398_17-134: SLOT17.E41
GX1X_3399_17-135: SLOT17.F41
GX1X_3400_17-136: SLOT17.Z41
GX1X_3401_17-137: SLOT17.Z39
GX1X_3402_17-138: SLOT17.A39
GX1X_3403_17-139: SLOT17.B39
GX1X_3404_17-140: SLOT17.C39
GX1X_3405_17-141: SLOT17.D39
GX1X_3406_17-142: SLOT17.E39
GX1X_3407_17-143: SLOT17.F39
GX1X_3408_17-144: SLOT17.A17
GX1X_3409_17-145: SLOT17.B17
GX1X_3410_17-146: SLOT17.C17
GX1X_3411_17-147: SLOT17.D17
GX1X_3412_17-148: SLOT17.E17
GX1X_3413_17-149: SLOT17.F17
GX1X_3414_17-150: SLOT17.A15
GX1X_3415_17-151: SLOT17.B15
GX1X_3416_17-152: SLOT17.C15
GX1X_3417_17-153: SLOT17.D15
GX1X_3418_17-154: SLOT17.E15
